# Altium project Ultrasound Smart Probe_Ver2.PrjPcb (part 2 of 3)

## Sheet Sht04--FPGA Power Supply.SchDoc: LVPS FPGA
size 431 x 279 mm; Date: Not shown in title block; ApprovedBy: Not shown in title block; CheckedBy: Not shown in title block; Author: Not shown in title block; CompanyName: Not shown in title block; DrawnBy: Bill.Xu; Engineer: Bill.Xu; Organization: Not shown in title block; Address1: Not shown in title block; Address2: Not shown in title block; Address3: Not shown in title block; Address4: Not shown in title block; DocumentNumber: 1; Revision: Use project parameter SCH_Rev; SheetNumber: 4; SheetTotal: 7; PageSetup: Record=PageOptions¦CenterHorizontal=True¦CenterVertical=True¦PrintScale=1.00¦XCorrection=1.00¦YCorrection=1.00¦PrintKind=0¦BorderSize=5000000¦LeftOffset=0¦BottomOffset=0¦Orientation=2¦PaperLength=1000¦PaperWidth=1000¦Scale=100¦PaperSource=15¦PrintQuality=600¦MediaType=1¦DitherType=10¦PaperKind=Letter¦PrintScaleMode=1
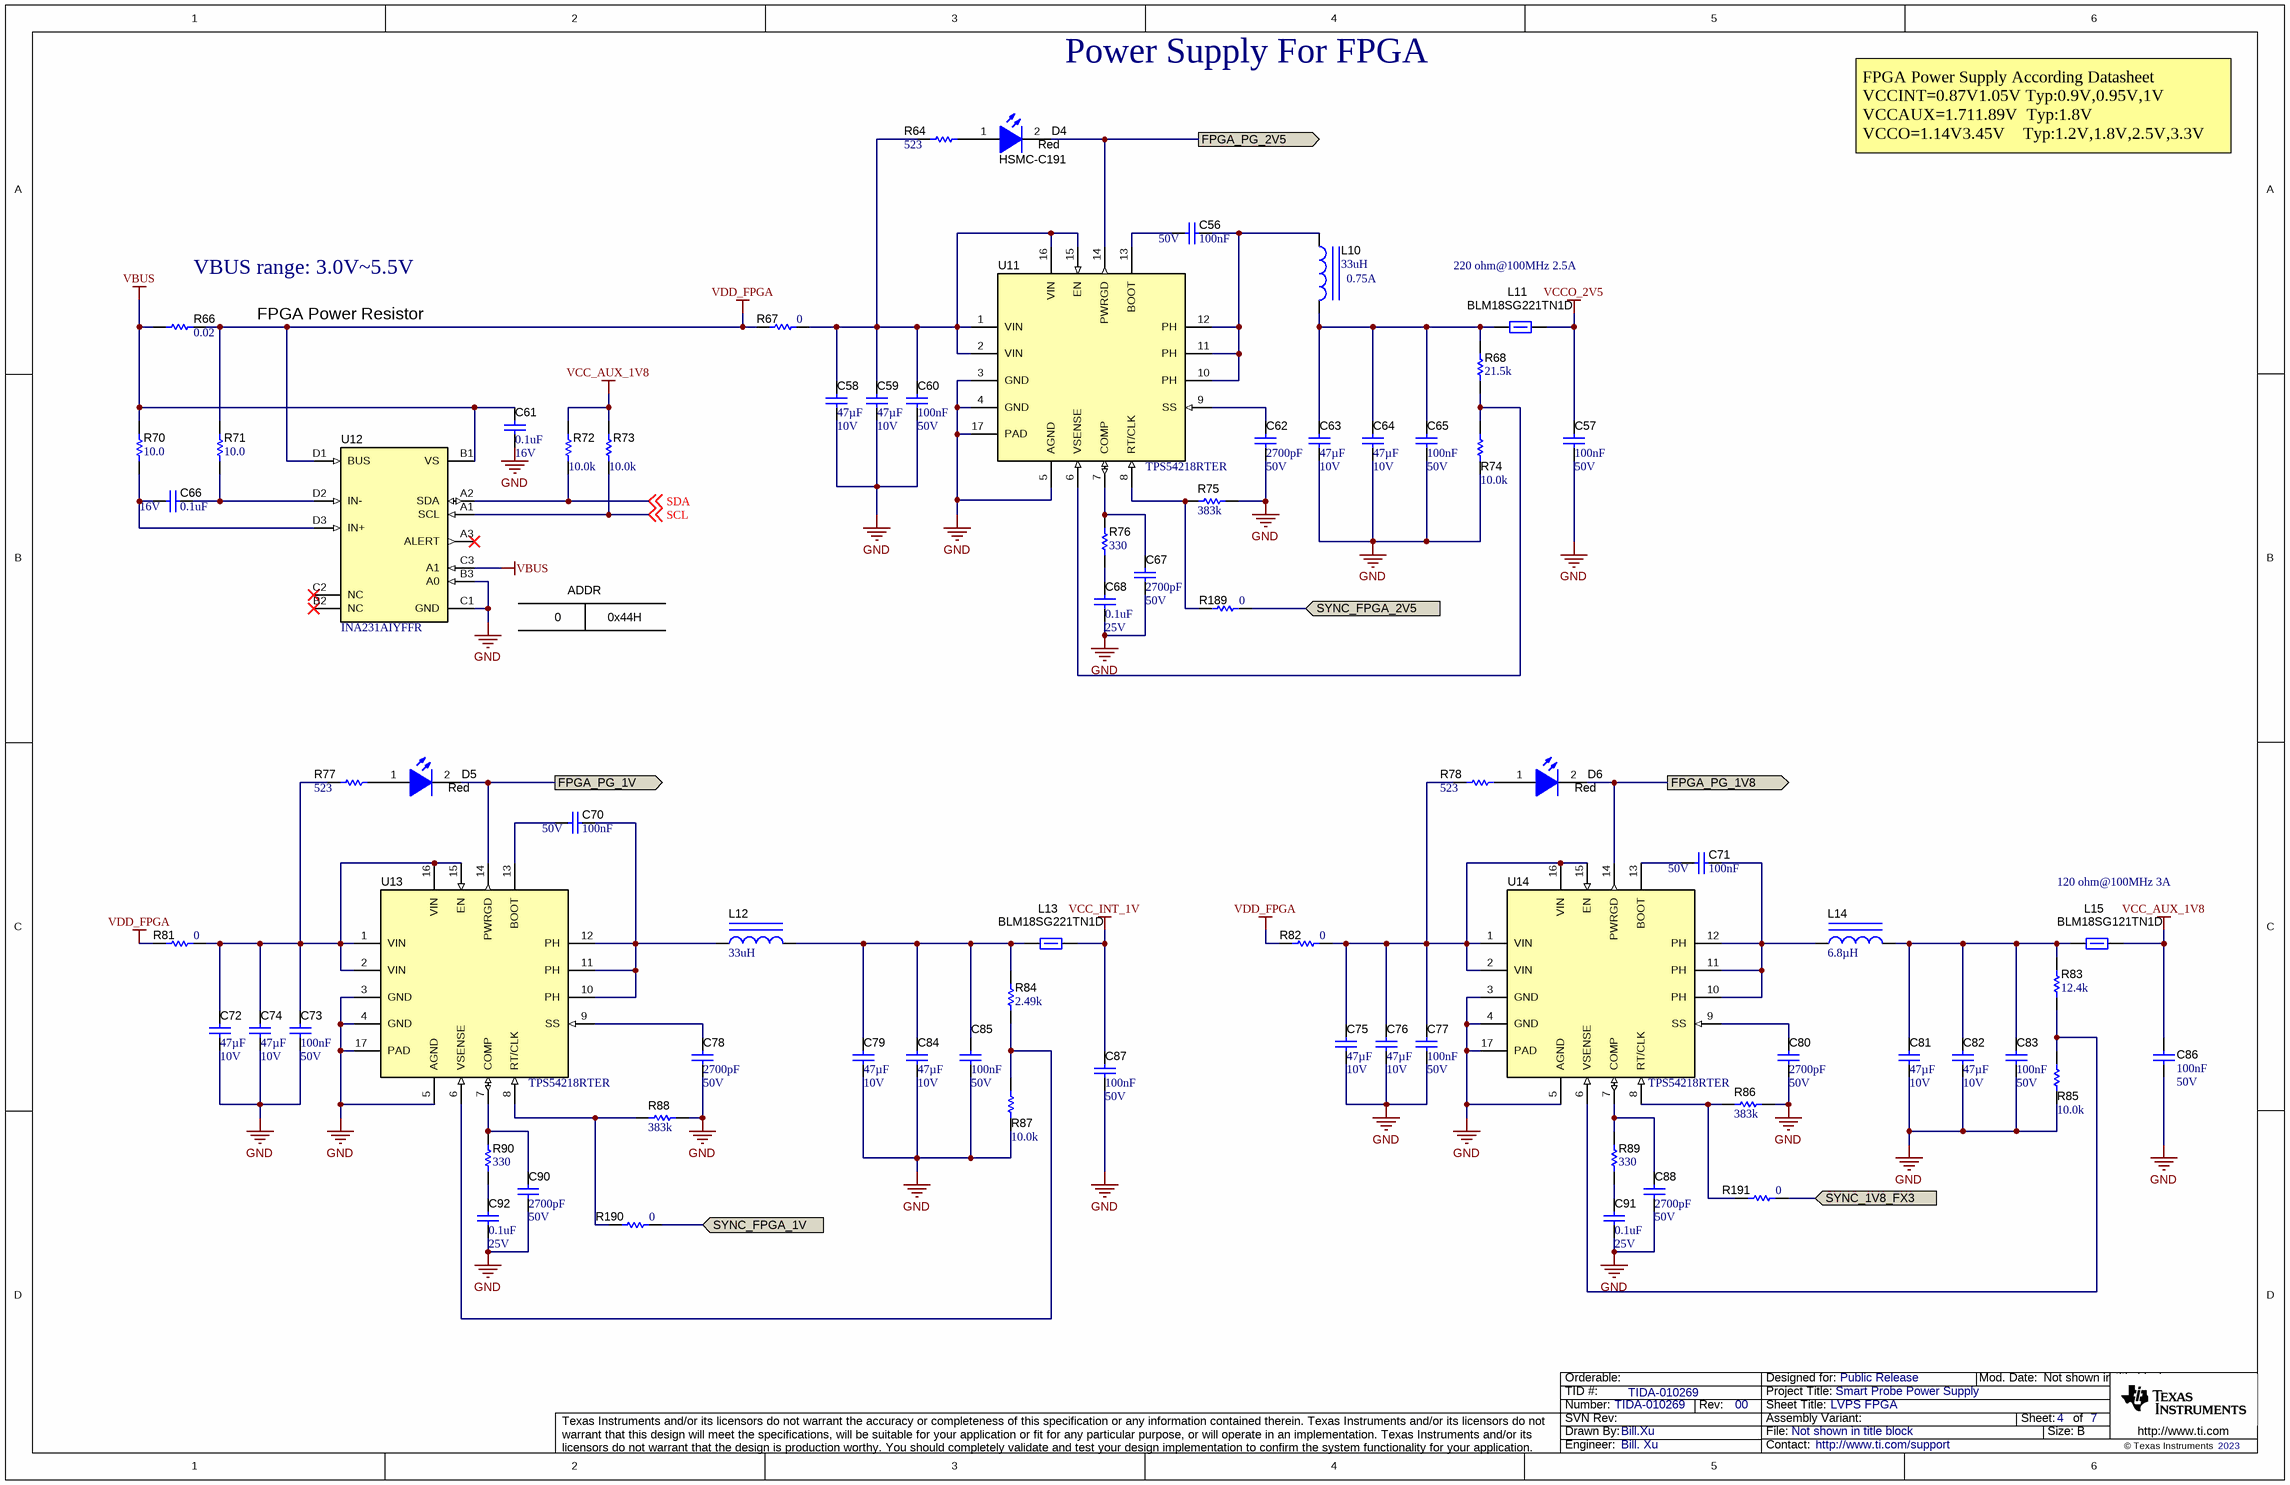
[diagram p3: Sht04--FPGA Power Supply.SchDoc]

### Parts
C56  Cap_F: 100nF  VDC_V: 50V  [0603]  (hidden comment: 885012206095)
C57  Cap_F: 100nF  VDC_V: 50V  [0603]  (hidden comment: 885012206095)
C58  VDC_V: 10V  ValueDisplayed: 47µF  [0805_HV]  (hidden comment: GRM21BR61A476ME15L)
C59  VDC_V: 10V  ValueDisplayed: 47µF  [0805_HV]  (hidden comment: GRM21BR61A476ME15L)
C60  Cap_F: 100nF  VDC_V: 50V  [0603]  (hidden comment: 885012206095)
C61  VDC_V: 16V  ValueDisplayed: 0.1uF  [0201_033]  (hidden comment: C0603X6S1C104K030BC)
C62  VDC_V: 50V  ValueDisplayed: 2700pF  [0402]  (hidden comment: GRM155R71H272KA01D)
C63  VDC_V: 10V  ValueDisplayed: 47µF  [0805_HV]  (hidden comment: GRM21BR61A476ME15L)
C64  VDC_V: 10V  ValueDisplayed: 47µF  [0805_HV]  (hidden comment: GRM21BR61A476ME15L)
C65  Cap_F: 100nF  VDC_V: 50V  [0603]  (hidden comment: 885012206095)
C66  VDC_V: 16V  ValueDisplayed: 0.1uF  [0201_033]  (hidden comment: C0603X6S1C104K030BC)
C67  VDC_V: 50V  ValueDisplayed: 2700pF  [0402]  (hidden comment: GRM155R71H272KA01D)
C68  VDC_V: 25V  ValueDisplayed: 0.1uF  [0402]  (hidden comment: GRM155R61E104KA87D)
C70  Cap_F: 100nF  VDC_V: 50V  [0603]  (hidden comment: 885012206095)
C71  Cap_F: 100nF  VDC_V: 50V  [0603]  (hidden comment: 885012206095)
C72  VDC_V: 10V  ValueDisplayed: 47µF  [0805_HV]  (hidden comment: GRM21BR61A476ME15L)
C73  Cap_F: 100nF  VDC_V: 50V  [0603]  (hidden comment: 885012206095)
C74  VDC_V: 10V  ValueDisplayed: 47µF  [0805_HV]  (hidden comment: GRM21BR61A476ME15L)
C75  VDC_V: 10V  ValueDisplayed: 47µF  [0805_HV]  (hidden comment: GRM21BR61A476ME15L)
C76  VDC_V: 10V  ValueDisplayed: 47µF  [0805_HV]  (hidden comment: GRM21BR61A476ME15L)
C77  Cap_F: 100nF  VDC_V: 50V  [0603]  (hidden comment: 885012206095)
C78  VDC_V: 50V  ValueDisplayed: 2700pF  [0402]  (hidden comment: GRM155R71H272KA01D)
C79  VDC_V: 10V  ValueDisplayed: 47µF  [0805_HV]  (hidden comment: GRM21BR61A476ME15L)
C80  VDC_V: 50V  ValueDisplayed: 2700pF  [0402]  (hidden comment: GRM155R71H272KA01D)
C81  VDC_V: 10V  ValueDisplayed: 47µF  [0805_HV]  (hidden comment: GRM21BR61A476ME15L)
C82  VDC_V: 10V  ValueDisplayed: 47µF  [0805_HV]  (hidden comment: GRM21BR61A476ME15L)
C83  Cap_F: 100nF  VDC_V: 50V  [0603]  (hidden comment: 885012206095)
C84  VDC_V: 10V  ValueDisplayed: 47µF  [0805_HV]  (hidden comment: GRM21BR61A476ME15L)
C85  Cap_F: 100nF  VDC_V: 50V  [0603]  (hidden comment: 885012206095)
C86  Cap_F: 100nF  VDC_V: 50V  [0402]  (hidden comment: GRM155R61E104KA87D)
C87  Cap_F: 100nF  VDC_V: 50V  [0402]  (hidden comment: GRM155R61E104KA87D)
C88  VDC_V: 50V  ValueDisplayed: 2700pF  [0402]  (hidden comment: GRM155R71H272KA01D)
C90  VDC_V: 50V  ValueDisplayed: 2700pF  [0402]  (hidden comment: GRM155R71H272KA01D)
C91  VDC_V: 25V  ValueDisplayed: 0.1uF  [0402]  (hidden comment: GRM155R61E104KA87D)
C92  VDC_V: 25V  ValueDisplayed: 0.1uF  [0402]  (hidden comment: GRM155R61E104KA87D)
D4  HSMC-C191  value Red  [HSMx-C191_Red]
D5  value Red  [HSMx-C191_Red]  (hidden comment: HSMC-C191)
D6  value Red  [HSMx-C191_Red]  (hidden comment: HSMC-C191)
L10  ValueDisplayed: 33uH  [WE-TPC-LH]  (hidden comment: 744053330)
L11  BLM18SG221TN1D  [0603]
L12  ValueDisplayed: 33uH  [WE-TPC-LH]  (hidden comment: 744053330)
L13  BLM18SG221TN1D  [0603]
L14  ValueDisplayed: 6.8µH  [NRS5030]  (hidden comment: NRS5030T6R8MMGJV)
L15  BLM18SG121TN1D  [0603]
R64  ValueDisplayed: 523  [0402]  (hidden comment: CRCW0402523RFKED)
R66  ValueDisplayed: 0.02  [WSLP0805]  (hidden comment: WSLP0805R0200FEB)
R67  ValueDisplayed: 0  [0805_HV]  (hidden comment: RC0805JR-070RL)
R68  ValueDisplayed: 21.5k  [0201]  (hidden comment: RC0201FR-0721K5L)
R70  ValueDisplayed: 10.0  [0201]  (hidden comment: RC0201FR-7D10RL)
R71  ValueDisplayed: 10.0  [0201]  (hidden comment: RC0201FR-7D10RL)
R72  ValueDisplayed: 10.0k  [0201]  (hidden comment: RC0201FS-7D10KL)
R73  ValueDisplayed: 10.0k  [0201]  (hidden comment: RC0201FS-7D10KL)
R74  ValueDisplayed: 10.0k  [0201]  (hidden comment: RC0201FS-7D10KL)
R75  ValueDisplayed: 383k  [0201]  (hidden comment: RC0201FR-07383KL)
R76  ValueDisplayed: 330  [0402]  (hidden comment: CRCW0402160RJNED)
R77  ValueDisplayed: 523  [0402]  (hidden comment: CRCW0402523RFKED)
R78  ValueDisplayed: 523  [0402]  (hidden comment: CRCW0402523RFKED)
R81  ValueDisplayed: 0  [0805_HV]  (hidden comment: RC0805JR-070RL)
R82  ValueDisplayed: 0  [0805_HV]  (hidden comment: RC0805JR-070RL)
R83  ValueDisplayed: 12.4k  [0201]  (hidden comment: RC0201FR-0712K4L)
R84  ValueDisplayed: 2.49k  [0201]  (hidden comment: RC0201FR-7D2K49L)
R85  ValueDisplayed: 10.0k  [0201]  (hidden comment: RC0201FS-7D10KL)
R86  ValueDisplayed: 383k  [0201]  (hidden comment: RC0201FR-07383KL)
R87  ValueDisplayed: 10.0k  [0201]  (hidden comment: RC0201FS-7D10KL)
R88  ValueDisplayed: 383k  [0201]  (hidden comment: RC0201FR-07383KL)
R89  ValueDisplayed: 330  [0402]  (hidden comment: CRCW0402160RJNED)
R90  ValueDisplayed: 330  [0402]  (hidden comment: CRCW0402160RJNED)
R189  ValueDisplayed: 0  [0201]  (hidden comment: CRCW02010000Z0ED)
R190  ValueDisplayed: 0  [0201]  (hidden comment: CRCW02010000Z0ED)
R191  ValueDisplayed: 0  [0201]  (hidden comment: CRCW02010000Z0ED)
U11  TPS54218RTER  [RTE0016F]
U12  INA231AIYFFR  [YFF0012AKAD]
U13  TPS54218RTER  [RTE0016F]
U14  TPS54218RTER  [RTE0016F]

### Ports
FPGA_PG_1V8 (out), FPGA_PG_1V (out), FPGA_PG_2V5 (out), SYNC_1V8_FX3 (in), SYNC_FPGA_1V (in), SYNC_FPGA_2V5 (in)

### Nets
GND: C57.2 C58.2 C59.2 C60.2 C61.2 C62.2 C63.2 C64.2 C65.2 C67.2 C68.2 C72.2 C73.2 C74.2 C75.2 C76.2 C77.2 C78.2 C79.2 C80.2 C81.2 C82.2 C83.1 C84.2 C85.2 C86.2 C87.2 C88.2 C90.2 C91.2 C92.2 R74.1 R75.2 R85.1 R86.2 R87.1 R88.2 U11.3(GND) U11.4(GND) U11.5(AGND) U11.17(PAD) U12.B3(A0) U12.C1(GND) U13.3(GND) U13.4(GND) U13.5(AGND) U13.17(PAD) U14.3(GND) U14.4(GND) U14.5(AGND) U14.17(PAD)
VBUS: C61.1 R66.1 R70.2 U12.B1(VS) U12.C3(A1)
VCC_AUX_1V8: C86.1 L15.2 R72.2 R73.2
VCC_INT_1V: C87.1 L13.2
VCCO_2V5: C57.1 L11.2
VDD_FPGA: R66.2 R67.1 R71.2 R81.1 R82.1 U12.D1(BUS)
FPGA_PG_1V: D5.2(K) U13.14(PWRGD) ; port FPGA_PG_1V
FPGA_PG_1V8: D6.2(K) U14.14(PWRGD) ; port FPGA_PG_1V8
FPGA_PG_2V5: D4.2(K) U11.14(PWRGD) ; port FPGA_PG_2V5
SCL: R73.1 U12.A1(SCL) ; off-sheet SCL
SDA: R72.1 U12.A2(SDA) ; off-sheet SDA
SYNC_1V8_FX3: R191.2 ; port SYNC_1V8_FX3
SYNC_FPGA_1V: R190.2 ; port SYNC_FPGA_1V
SYNC_FPGA_2V5: R189.2 ; port SYNC_FPGA_2V5
NetC56_1: C56.1 L10.1 U11.10(PH) U11.11(PH) U11.12(PH)
NetC56_2: C56.2 U11.13(BOOT)
NetC58_1: C58.1 C59.1 C60.1 R64.1 R67.2 U11.1(VIN) U11.2(VIN) U11.15(EN) U11.16(VIN)
NetC62_1: C62.1 U11.9(SS)
NetC63_1: C63.1 C64.1 C65.1 L10.2 L11.1 R68.2
NetC66_1: C66.1 R70.1 U12.D3(IN+)
NetC66_2: C66.2 R71.1 U12.D2(IN-)
NetC67_1: C67.1 R76.2 U11.7(COMP)
NetC68_1: C68.1 R76.1
NetC70_1: C70.1 L12.1 U13.10(PH) U13.11(PH) U13.12(PH)
NetC70_2: C70.2 U13.13(BOOT)
NetC71_1: C71.1 L14.1 U14.10(PH) U14.11(PH) U14.12(PH)
NetC71_2: C71.2 U14.13(BOOT)
NetC72_1: C72.1 C73.1 C74.1 R77.1 R81.2 U13.1(VIN) U13.2(VIN) U13.15(EN) U13.16(VIN)
NetC75_1: C75.1 C76.1 C77.1 R78.1 R82.2 U14.1(VIN) U14.2(VIN) U14.15(EN) U14.16(VIN)
NetC78_1: C78.1 U13.9(SS)
NetC79_1: C79.1 C84.1 C85.1 L12.2 L13.1 R84.2
NetC80_1: C80.1 U14.9(SS)
NetC81_1: C81.1 C82.1 C83.2 L14.2 L15.1 R83.2
NetC88_1: C88.1 R89.2 U14.7(COMP)
NetC90_1: C90.1 R90.2 U13.7(COMP)
NetC91_1: C91.1 R89.1
NetC92_1: C92.1 R90.1
NetD4_1: D4.1(A) R64.2
NetD5_1: D5.1(A) R77.2
NetD6_1: D6.1(A) R78.2
NetR68_1: R68.1 R74.2 U11.6(VSENSE)
NetR75_1: R75.1 R189.1 U11.8(RT/CLK)
NetR83_1: R83.1 R85.2 U14.6(VSENSE)
NetR84_1: R84.1 R87.2 U13.6(VSENSE)
NetR86_1: R86.1 R191.1 U14.8(RT/CLK)
NetR88_1: R88.1 R190.1 U13.8(RT/CLK)

Not connected (* = marked no-connect by the designer): U12 A3(ALERT)* B2(NC)* C2(NC)*

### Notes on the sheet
- Power Supply For FPGA
- FPGA Power Supply According Datasheet
  VCCINT=0.87V1.05V Typ:0.9V,0.95V,1V
  VCCAUX=1.711.89V  Typ:1.8V
  VCCO=1.14V3.45V    Typ:1.2V,1.8V,2.5V,3.3V
- (near R66) VBUS range: 3.0V~5.5V
- (near L10) 0.75A
- 220 ohm@100MHz 2.5A
- FPGA Power Resistor
- 0
- ADDR
- 0x44H
- 120 ohm@100MHz 3A

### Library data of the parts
C56 C57 C60 C65 C70 C71 C73 C77 C83 C85 = CMP-0006837-2: CAP, CERM, 0.1 uF, 50 V, +/- 10%, X7R, 0603; Manufacturer: Wurth Elektronik; TaMin_C: -55°C; Polarized: N; SizeAreaWB_mm2: 4.68; Value1: Unknown; U/M: EA; Value: 0.1uF; TaMax_C: 125°C; SizeZ_mm: 1; SizeX_mm: 1.6; SizeY_mm: 0.8; SizeArea_mm2: 1.28; AEC Category: Q200
C58 C59 C63 C64 C72 C74-C76 C79 C81 C82 C84 = CMP-0078699-1: CAP, CERM, 47 µF, 10 V,+/- 20%, X5R, 0805; Manufacturer: MuRata; TaMin_C: -55°C; Polarized: N; Green_Lifecycle: Active; SizeAreaWB_mm2: 6.75; Green_REACh: Passed; U/M: EA; Value: 47uF; TaMax_C: 85°C; SizeZ_mm: 1.45; SizeX_mm: 2; SizeY_mm: 1.25; Cap_Case: 0805; SizeArea_mm2: 2.5; AEC Category: Q200
C61 C66 = CMP-0009637-1: CAP, CERM, 0.1 uF, 16 V, +/- 10%, X6S, 0201; Manufacturer: TDK; TaMin_C: -55°C; Polarized: N; SizeAreaWB_mm2: 2.08; Value1: Unknown; U/M: EA; Value: 0.1uF; TaMax_C: 105°C; SizeZ_mm: 0.33; SizeX_mm: 0.6; SizeY_mm: 0.3; Cap_Case: 0201; SizeArea_mm2: 0.18; Cap_F: 100nF; AEC Category: Q200
C62 C67 C78 C80 C88 C90 = CMP-0006686-1: CAP, CERM, 2700 pF, 50 V, +/- 10%, X7R, 0402; Manufacturer: MuRata; TaMin_C: -55°C; Polarized: N; SizeAreaWB_mm2: 3; Value1: Unknown; U/M: EA; Value: 2700pF; TaMax_C: 125°C; SizeZ_mm: 0.6; SizeX_mm: 1; SizeY_mm: 0.5; Cap_F: 2.7nF; AEC Category: Q200
C68 C91 C92 = CMP-0006607-1: CAP, CERM, 0.1 uF, 25 V, +/- 10%, X5R, 0402; Manufacturer: MuRata; TaMin_C: -55°C; Polarized: N; SizeAreaWB_mm2: 3; Value1: Unknown; U/M: EA; Value: 0.1uF; TaMax_C: 85°C; SizeZ_mm: 0.6; SizeX_mm: 1; SizeY_mm: 0.5; Cap_F: 100nF; AEC Category: Q200
C86 C87 = CMP-0006837-2: CAP, CERM, 0.1 uF, 50 V, +/- 10%, X7R, 0603; Manufacturer: Wurth Elektronik; PartNumber: 885012206095; TaMin_C: -55°C; Polarized: N; SizeAreaWB_mm2: 4.68; Value1: Unknown; U/M: EA; Value: 0.1uF; TaMax_C: 125°C; SizeZ_mm: 1; SizeX_mm: 1.6; SizeY_mm: 0.8; Cap_Case: 0603; SizeArea_mm2: 1.28; AEC Category: Q200
D4-D6 = CMP-0078541-2: LED, Red, SMD; Manufacturer: Avago; Vf_V: 1.9V; SizeX_mm: 1.6; SizeY_mm: 0.8; Tjmax_C: 95°C; Io_A: 20mA; SizeAreaWB_mm2: 4.68; Value1: W; Angle: 170; SizeArea_mm2: 1.28; Vr_V: 5V; Type: AlInGaP; SizeZ_mm: 0.7
L10 L12 = CMP-0064424-1: Inductor, Shielded Drum Core, Ferrite, 33 uH, 0.75 A, 0.155 ohm, SMD; Manufacturer: Wurth Elektronik; Isat: 0.75A @ 35% inductance drop; Irms: 0.9A @ 30C rise; Green_Lifecycle: Active; SizeAreaWB_mm2: 60.84; DCR_ohm: 0.155; Green_REACh: Passed; Value: 33uH; Imax_A: 750mA; SizeZ_mm: 2.8; SizeX_mm: 5.8; Value2: 0.75A; SizeArea_mm2: 33.64; Ind_H: 33µH; AEC Category: Q200
L11 L13 = CMP-0003353-1: Ferrite Bead, 220 ohm @ 100 MHz, 2.5 A, 0603; Manufacturer: MuRata; ZTyp@100MHz_Ohm: 220; SizeAreaWB_mm2: 4.68; DCR_ohm: 40m; Value1: 0.04 ohm; Value: 220 ohm; Imax_A: 2.5A; SizeZ_mm: 1; SizeX_mm: 1.6; SizeY_mm: 0.8; SizeArea_mm2: 1.28
L14 = CMP-0081757-1: Inductor, Shielded, Ferrite, 6.8 µH, 2.3 A, 0.0676 ohm, AEC-Q200 Grade 1, SMD; Manufacturer: Taiyo Yuden; Isat: 2.5A @ 30% inductance drop; Irms: 2A @ 40C rise; SizeAreaWB_mm2: 34.81; DCR_ohm: 67.6m; Value: 6.8uH; Imax_A: 2.3A; SizeZ_mm: 3.1; SizeX_mm: 4.9; SizeArea_mm2: 24.01; AEC Qualified: Y; AEC Grade: 1; AEC Category: Q200
L15 = CMP-0003352-2: Ferrite Bead, 120 ohm @ 100 MHz, 3 A, 0603; Manufacturer: MuRata; ZTyp@100MHz_Ohm: 120; SizeAreaWB_mm2: 4.68; DCR_ohm: 25m; Value1: 0.025 ohm; Value: 120 ohm; Imax_A: 3A; SizeZ_mm: 1; SizeX_mm: 1.6; SizeY_mm: 0.8; SizeArea_mm2: 1.28
R64 R77 R78 = CMP-0026440-2: RES, 523, 1%, 0.063 W, AEC-Q200 Grade 0, 0402; Manufacturer: Vishay-Dale; Power_W: 63mW; TempCo: 100 ppm/C; Value_Code: 523R; Value: 523; EIA_Code: E96; SizeX_mm: 1; SizeY_mm: 0.5; SizeZ_mm: 0.6; Value2: 0.063W; AEC Qualified: Y; VDC_V: 50V; AEC Category: Q200; AEC Grade: 0
R66 = CMP-0021986-1: RES, 0.02, 1%, 0.5 W, 0805; Manufacturer: Vishay-Dale; Power_W: 500mW; TempCo: 75 ppm/C; Value_Code: R020; U/M: EA; Value: 0.02; EIA_Code: E96; Res_ohm: 20m; SizeX_mm: 2.03; SizeY_mm: 1.27; SizeZ_mm: 0.635; Value2: 0.5W; SizeArea_mm2: 2.5781; AEC Qualified: N; AEC Category: Q200
R67 R81 R82 = CMP-0020803-2: RES, 0, 5%, 0.125 W, 0805; Manufacturer: Yageo America; Power_W: 125mW; TempCo: 200 ppm/C; Value_Code: 0000; U/M: EA; Value: 0; EIA_Code: E24; SizeX_mm: 2; SizeY_mm: 1.25; SizeZ_mm: 1.45; Value2: 0.125W; SizeArea_mm2: 2.5; VDC_V: 150V; AEC Category: Q200
R68 = CMP-0027485-1: RES, 21.5 k, 1%, 0.05 W, 0201; Manufacturer: Yageo America; Power_W: 50mW; TempCo: 200 ppm/C; Value_Code: 21k5; U/M: EA; Value: 21.5k; EIA_Code: E96; SizeX_mm: 0.6; SizeY_mm: 0.3; SizeZ_mm: 0.26; Value2: 0.05W; SizeArea_mm2: 0.18; AEC Qualified: N; VDC_V: 25V; AEC Category: Q200
R70 R71 = CMP-0027946-1: RES, 10.0, 1%, 0.05 W, 0201; Manufacturer: Yageo America; Power_W: 50mW; TempCo: 350 ppm/C; Value_Code: 10R0; U/M: EA; Value: 10.0; EIA_Code: E96; Res_ohm: 10; SizeX_mm: 0.6; SizeY_mm: 0.3; SizeZ_mm: 0.26; Value2: 0.05W; SizeArea_mm2: 0.18; AEC Qualified: N; VDC_V: 25V; AEC Category: Q200
R72-R74 R85 R87 = CMP-0028071-1: RES SMD 10K OHM 1% 1/20W 0201; Manufacturer: Samsung Electro-Mechanics; PartNumber: RC0603F103CS; Power_W: 50mW; TempCo: 200 ppm/C; Value_Code: 10k0; U/M: EA; Value: 10.0k; EIA_Code: E96; SizeX_mm: 0.6; SizeY_mm: 0.3; SizeZ_mm: 0.26; Value2: 0.05W; SizeArea_mm2: 0.18; AEC Qualified: N; VDC_V: 25V; AEC Category: Q200
R75 R86 R88 = CMP-0027640-1: RES, 383 k, 1%, 0.05 W, 0201; Manufacturer: Yageo America; Power_W: 50mW; TempCo: 200 ppm/C; U/M: EA; Value: 383k; EIA_Code: E96; SizeX_mm: 0.6; SizeY_mm: 0.3; SizeZ_mm: 0.26; Value2: 0.05W; SizeArea_mm2: 0.18; AEC Qualified: N; VDC_V: 25V; AEC Category: Q200
R76 R89 R90 = CMP-0026845-3: RES SMD 330 OHM 1% 1/10W 0402; Manufacturer: Panasonic Electronic Components; PartNumber: ERJ-2RKF3300X; Power_W: 63mW; TempCo: 200 ppm/C; Value_Code: 160R; Value1: 5%; Value: 160; EIA_Code: E24; SizeX_mm: 1; SizeY_mm: 0.5; SizeZ_mm: 0.6; Value2: 0.063W; AEC Qualified: Y; VDC_V: 50V; AEC Category: Q200; AEC Grade: 0
R83 = CMP-0027335-2: RES, 12.4 k, 1%, 0.05 W, 0201; Manufacturer: Yageo America; Power_W: 50mW; TempCo: 200 ppm/C; Value_Code: 12k4; U/M: EA; Value: 12.4k; EIA_Code: E96; SizeX_mm: 0.6; SizeY_mm: 0.3; SizeZ_mm: 0.26; Value2: 0.05W; SizeArea_mm2: 0.18; AEC Qualified: N; VDC_V: 25V; AEC Category: Q200
R84 = CMP-0027996-1: RES, 2.49 k, 1%, 0.05 W, 0201; Manufacturer: Yageo America; Power_W: 50mW; TempCo: 200 ppm/C; Value_Code: 2k49; U/M: EA; Value: 2.49k; EIA_Code: E96; SizeX_mm: 0.6; SizeY_mm: 0.3; SizeZ_mm: 0.26; Value2: 0.05W; SizeArea_mm2: 0.18; AEC Qualified: N; VDC_V: 25V; AEC Category: Q200
R189-R191 = CMP-0027008-1: RES, 0, 5%, 0.05 W, 0201; Manufacturer: Vishay-Dale; Power_W: 50mW; TempCo: ppm/C; Value_Code: 0000; U/M: EA; Value: 0; EIA_Code: E24; SizeX_mm: 0.6; SizeY_mm: 0.3; SizeZ_mm: 0.26; Value2: 0.05W; SizeArea_mm2: 0.18; AEC Qualified: N; AEC Category: Q200
U11 U14 = CMP-0073970-3: 2.95V to 6V Input, 2A Synchronous Step-Down SWIFT(TM) Converter, RTE0016F (WQFN-16); Alternate PartNumber: TPS54218RTET; Alternate Manufacturer: Texas Instruments; Green_Lifecycle: Active; SizeAreaWB_mm2: 16.0; Green_REACh: Passed; SizeZ_mm: 0.8; SizeX_mm: 3.0; SizeArea_mm2: 9.0; CompType: IC; AEC Category: Q200; AEC Qualified: N
U12 = CMP-0065450-1: 28-V, Bi-Directional, Zero-Drift, Low-/High-Side, I2C Out Current/Power Monitor w/ Alert in WCSP, YFF0012AKAD (DSBGA-12); Alternate PartNumber: INA231AIYFFT; Alternate Manufacturer: Texas Instruments; Green_Lifecycle: Active; SizeAreaWB_mm2: 6.313872; Green_REACh: Passed; U/M: EA; SizeZ_mm: 0.625; SizeX_mm: 1.388; SizeY_mm: 1.644; SizeArea_mm2: 2.281872; CompType: IC
U13 = CMP-0073970-1: 2.95V to 6V Input, 2A Synchronous Step-Down SWIFT(TM) Converter, RTE0016F (WQFN-16); Alternate PartNumber: TPS54218RTET; Alternate Manufacturer: Texas Instruments; Green_Lifecycle: Active; SizeAreaWB_mm2: 16.0; Green_REACh: Passed; U/M: EA; SizeZ_mm: 0.8; SizeX_mm: 3.0; SizeArea_mm2: 9.0; CompType: IC

## Sheet Sht05--TX-RX Supply 1.8V and 1.15V.SchDoc: LVPS RX Supply 1.8V and 1.15V
size 431 x 279 mm; Date: Not shown in title block; ApprovedBy: Not shown in title block; CheckedBy: Not shown in title block; Author: Not shown in title block; CompanyName: Not shown in title block; DrawnBy: Bill.Xu; Engineer: Bill.Xu; Organization: Not shown in title block; Address1: Not shown in title block; Address2: Not shown in title block; Address3: Not shown in title block; Address4: Not shown in title block; DocumentNumber: 1; Revision: Use project parameter SCH_Rev; SheetNumber: 5; SheetTotal: 7; PageSetup: Record=PageOptions¦CenterHorizontal=True¦CenterVertical=True¦PrintScale=1.00¦XCorrection=1.00¦YCorrection=1.00¦PrintKind=0¦BorderSize=5000000¦LeftOffset=0¦BottomOffset=0¦Orientation=2¦PaperLength=1000¦PaperWidth=1000¦Scale=100¦PaperSource=15¦PrintQuality=600¦MediaType=1¦DitherType=10¦PaperKind=Letter¦PrintScaleMode=1
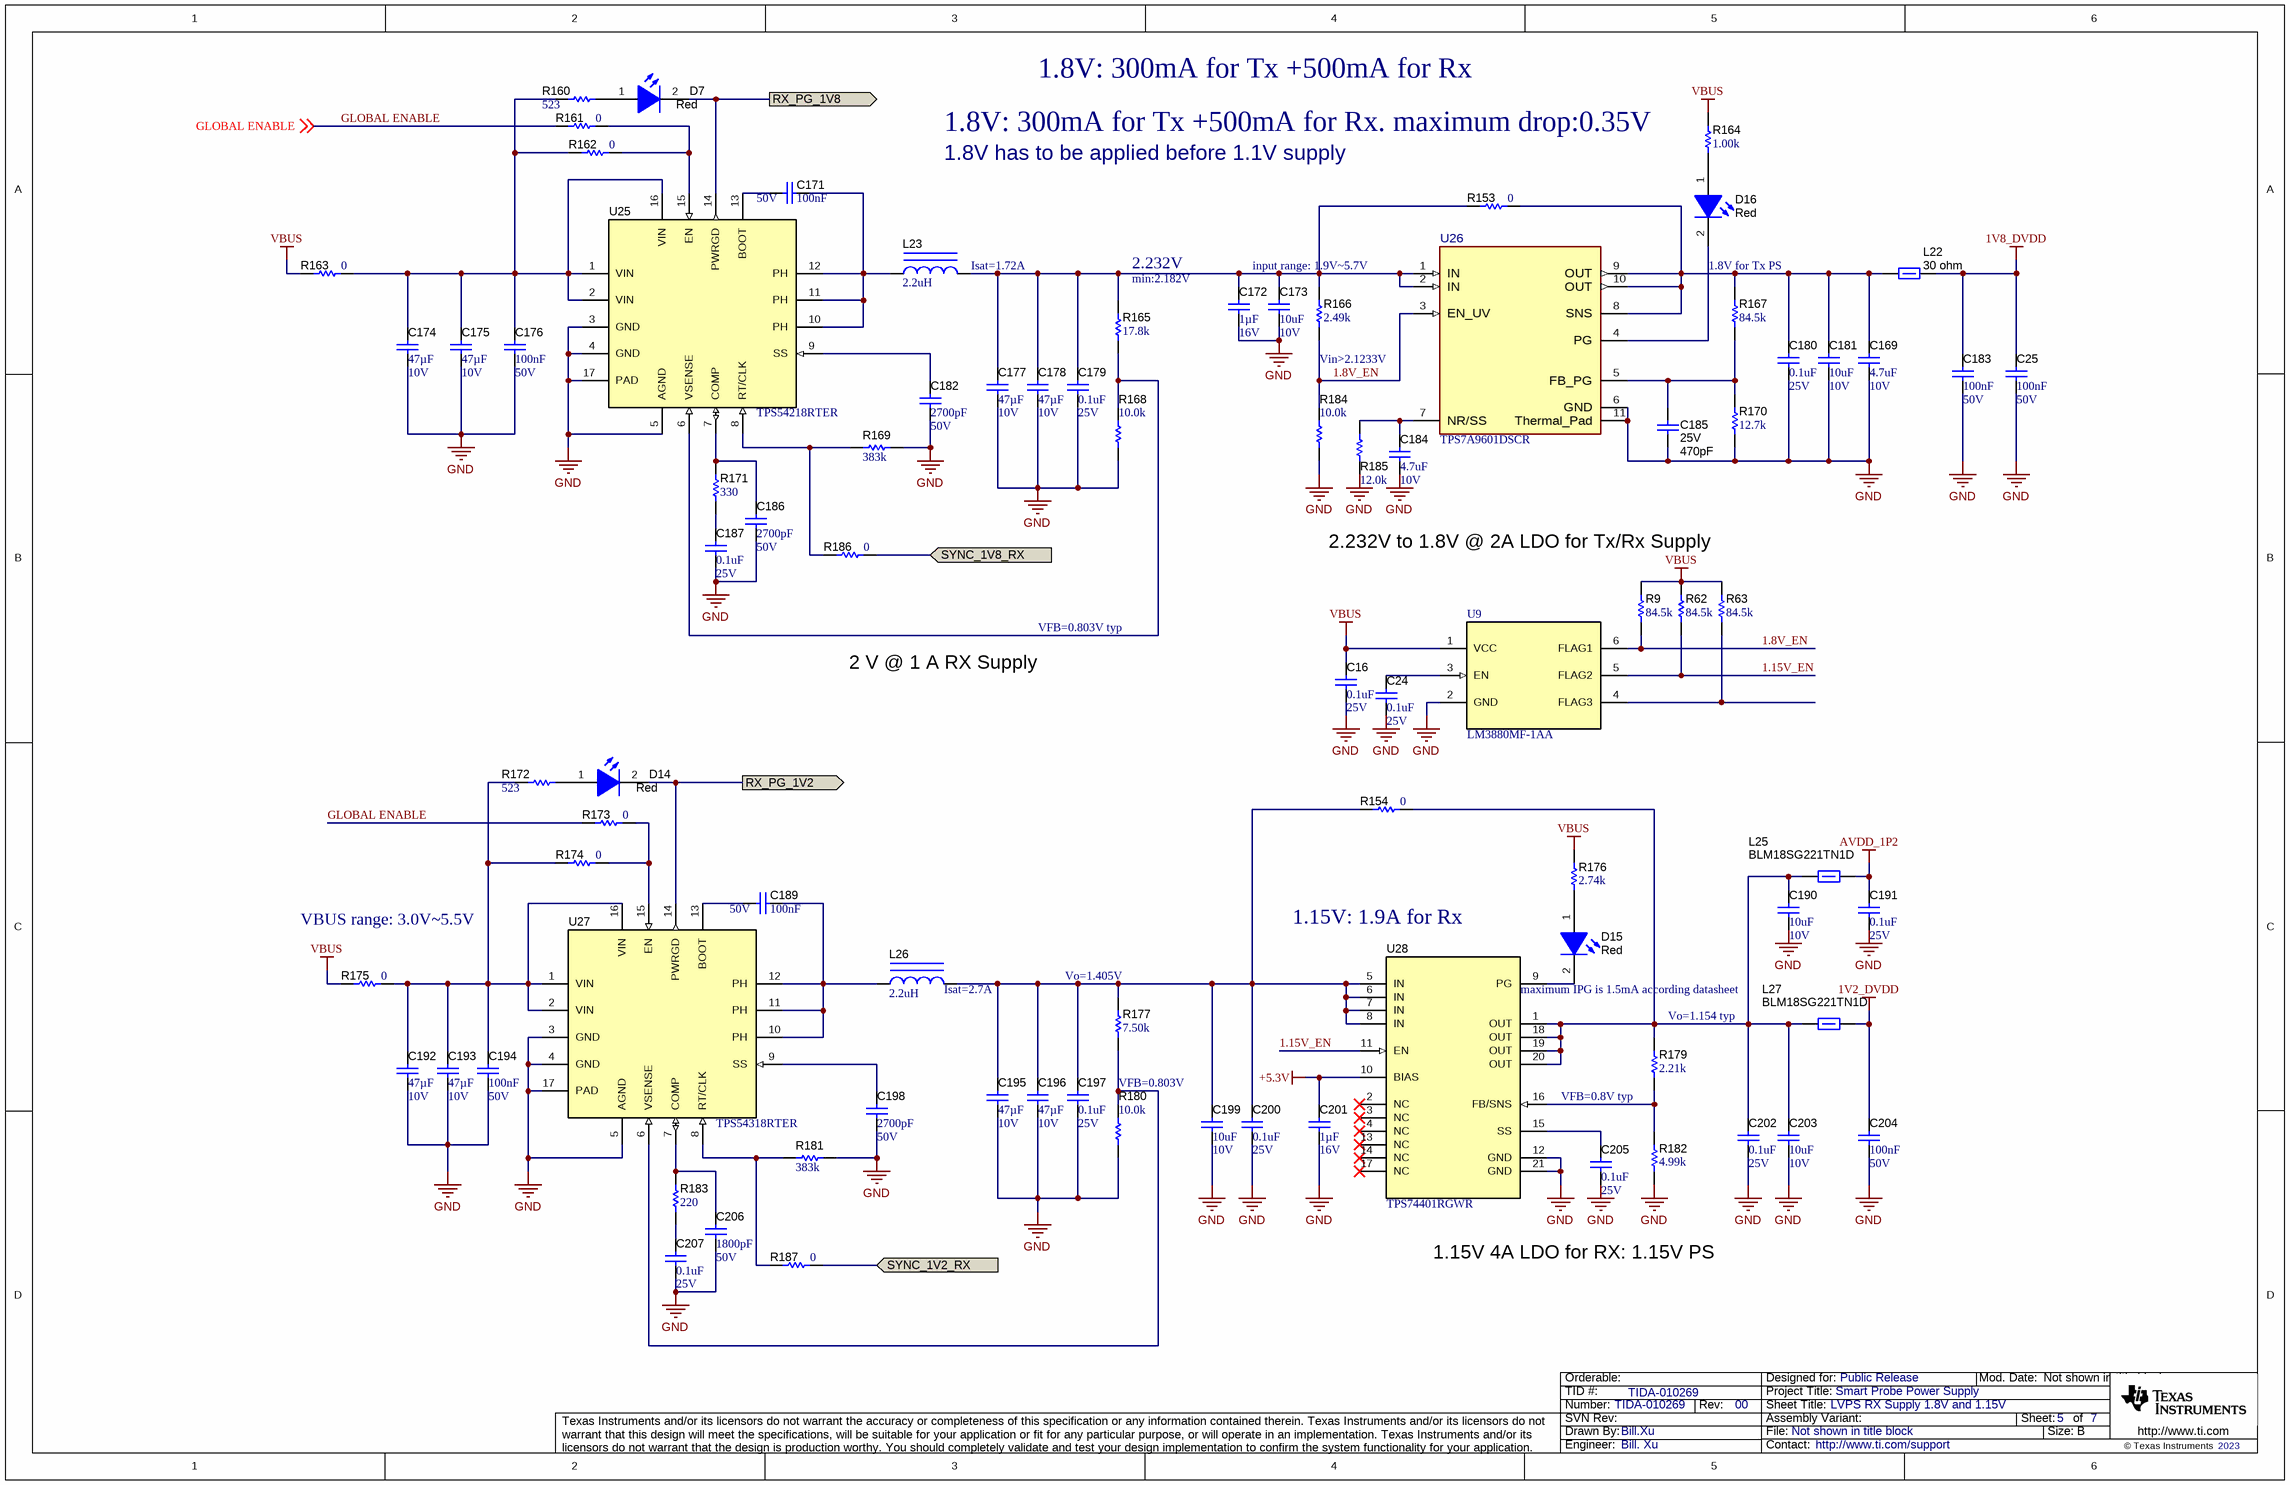
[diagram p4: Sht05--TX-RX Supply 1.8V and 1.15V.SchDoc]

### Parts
C16  VDC_V: 25V  ValueDisplayed: 0.1uF  [0402]  (hidden comment: GRM155R61E104KA87D)
C24  VDC_V: 25V  ValueDisplayed: 0.1uF  [0402]  (hidden comment: GRM155R61E104KA87D)
C25  Cap_F: 100nF  VDC_V: 50V  [0603]  (hidden comment: 885012206095)
C169  VDC_V: 10V  ValueDisplayed: 4.7uF  [0603]  (hidden comment: GRM188R61A475MAAJ)
C171  Cap_F: 100nF  VDC_V: 50V  [0603]  (hidden comment: 885012206095)
C172  Cap_F: 1µF  VDC_V: 16V  [0603]  (hidden comment: 885012206052)
C173  VDC_V: 10V  ValueDisplayed: 10uF  [0603]  (hidden comment: C1608X5R1A106M080AC)
C174  VDC_V: 10V  ValueDisplayed: 47µF  [0805_HV]  (hidden comment: GRM21BR61A476ME15L)
C175  VDC_V: 10V  ValueDisplayed: 47µF  [0805_HV]  (hidden comment: GRM21BR61A476ME15L)
C176  Cap_F: 100nF  VDC_V: 50V  [0603]  (hidden comment: 885012206095)
C177  VDC_V: 10V  ValueDisplayed: 47µF  [0805_HV]  (hidden comment: GRM21BR61A476ME15L)
C178  VDC_V: 10V  ValueDisplayed: 47µF  [0805_HV]  (hidden comment: GRM21BR61A476ME15L)
C179  VDC_V: 25V  ValueDisplayed: 0.1uF  [0402]  (hidden comment: GRM155R61E104KA87D)
C180  VDC_V: 25V  ValueDisplayed: 0.1uF  [0402]  (hidden comment: GRM155R61E104KA87D)
C181  VDC_V: 10V  ValueDisplayed: 10uF  [0603]  (hidden comment: C1608X5R1A106M080AC)
C182  VDC_V: 50V  ValueDisplayed: 2700pF  [0402]  (hidden comment: GRM155R71H272KA01D)
C183  Cap_F: 100nF  VDC_V: 50V  [0603]  (hidden comment: 885012206095)
C184  VDC_V: 10V  ValueDisplayed: 4.7uF  [0603]  (hidden comment: GRM188R61A475MAAJ)
C185  VDC_V: 25V  ValueDisplayed: 470pF  [0402]  (hidden comment: GRM1555C1E471JA01D)
C186  VDC_V: 50V  ValueDisplayed: 2700pF  [0402]  (hidden comment: GRM155R71H272KA01D)
C187  VDC_V: 25V  ValueDisplayed: 0.1uF  [0402]  (hidden comment: GRM155R61E104KA87D)
C189  Cap_F: 100nF  VDC_V: 50V  [0603]  (hidden comment: 885012206095)
C190  VDC_V: 10V  ValueDisplayed: 10uF  [0603]  (hidden comment: C1608X5R1A106M080AC)
C191  VDC_V: 25V  ValueDisplayed: 0.1uF  [0402]  (hidden comment: GRM155R61E104KA87D)
C192  VDC_V: 10V  ValueDisplayed: 47µF  [0805_HV]  (hidden comment: GRM21BR61A476ME15L)
C193  VDC_V: 10V  ValueDisplayed: 47µF  [0805_HV]  (hidden comment: GRM21BR61A476ME15L)
C194  Cap_F: 100nF  VDC_V: 50V  [0603]  (hidden comment: 885012206095)
C195  VDC_V: 10V  ValueDisplayed: 47µF  [0805_HV]  (hidden comment: GRM21BR61A476ME15L)
C196  VDC_V: 10V  ValueDisplayed: 47µF  [0805_HV]  (hidden comment: GRM21BR61A476ME15L)
C197  VDC_V: 25V  ValueDisplayed: 0.1uF  [0402]  (hidden comment: GRM155R61E104KA87D)
C198  VDC_V: 50V  ValueDisplayed: 2700pF  [0402]  (hidden comment: GRM155R71H272KA01D)
C199  VDC_V: 10V  ValueDisplayed: 10uF  [0603]  (hidden comment: C1608X5R1A106M080AC)
C200  VDC_V: 25V  ValueDisplayed: 0.1uF  [0402]  (hidden comment: GRM155R61E104KA87D)
C201  Cap_F: 1µF  VDC_V: 16V  [0603]  (hidden comment: 885012206052)
C202  VDC_V: 25V  ValueDisplayed: 0.1uF  [0402]  (hidden comment: GRM155R61E104KA87D)
C203  VDC_V: 10V  ValueDisplayed: 10uF  [0603]  (hidden comment: C1608X5R1A106M080AC)
C204  Cap_F: 100nF  VDC_V: 50V  [0402]  (hidden comment: GRM155R61E104KA87D)
C205  VDC_V: 25V  ValueDisplayed: 0.1uF  [0402]  (hidden comment: GRM155R61E104KA87D)
C206  VDC_V: 50V  ValueDisplayed: 1800pF  [0402]  (hidden comment: GRM155R71H182KA01D)
C207  VDC_V: 25V  ValueDisplayed: 0.1uF  [0402]  (hidden comment: GRM155R61E104KA87D)
D7  value Red  [HSMx-C191_Red]  (hidden comment: HSMC-C191)
D14  value Red  [HSMx-C191_Red]  (hidden comment: HSMC-C191)
D15  value Red  [HSMx-C191_Red]  (hidden comment: HSMC-C191)
D16  value Red  [HSMx-C191_Red]  (hidden comment: HSMC-C191)
L22  ValueDisplayed: 30 ohm  [0603]  (hidden comment: 742792609)
L23  ValueDisplayed: 2.2uH  [VLCF4020]  (hidden comment: VLCF4020T-2R2N1R7)
L25  BLM18SG221TN1D  [0603]
L26  ValueDisplayed: 2.2uH  [WE-TPC_6823]  (hidden comment: 744062002)
L27  BLM18SG221TN1D  [0603]
R9  ValueDisplayed: 84.5k  [0402]  (hidden comment: CRCW040284K5FKED)
R62  ValueDisplayed: 84.5k  [0402]  (hidden comment: CRCW040284K5FKED)
R63  ValueDisplayed: 84.5k  [0402]  (hidden comment: CRCW040284K5FKED)
R153  ValueDisplayed: 0  [0805_HV]  (hidden comment: RC0805JR-070RL)
R154  ValueDisplayed: 0  [0805_HV]  (hidden comment: RC0805JR-070RL)
R160  ValueDisplayed: 523  [0402]  (hidden comment: CRCW0402523RFKED)
R161  ValueDisplayed: 0  [0201]  (hidden comment: CRCW02010000Z0ED)
R162  ValueDisplayed: 0  [0201]  (hidden comment: CRCW02010000Z0ED)
R163  ValueDisplayed: 0  [0805_HV]  (hidden comment: RC0805JR-070RL)
R164  ValueDisplayed: 1.00k  [0402]  (hidden comment: CRCW04021K00FKED)
R165  ValueDisplayed: 17.8k  [0402]  (hidden comment: CRCW040217K8FKED)
R166  ValueDisplayed: 2.49k  [0402]  (hidden comment: CRCW04022K49FKED)
R167  ValueDisplayed: 84.5k  [0402]  (hidden comment: CRCW040284K5FKED)
R168  ValueDisplayed: 10.0k  [0201]  (hidden comment: RC0201FS-7D10KL)
R169  ValueDisplayed: 383k  [0402]  (hidden comment: CRCW0402383KFKED)
R170  ValueDisplayed: 12.7k  [0402]  (hidden comment: CRCW040212K7FKED)
R171  ValueDisplayed: 330  [0402]  (hidden comment: CRCW0402160RJNED)
R172  ValueDisplayed: 523  [0402]  (hidden comment: CRCW0402523RFKED)
R173  ValueDisplayed: 0  [0201]  (hidden comment: CRCW02010000Z0ED)
R174  ValueDisplayed: 0  [0201]  (hidden comment: CRCW02010000Z0ED)
R175  ValueDisplayed: 0  [0805_HV]  (hidden comment: RC0805JR-070RL)
R176  ValueDisplayed: 2.74k  [0402]  (hidden comment: CRCW04022K74FKED)
R177  ValueDisplayed: 7.50k  [0201]  (hidden comment: RC0201FR-077K5L)
R179  ValueDisplayed: 2.21k  [0402]  (hidden comment: CRCW04022K21FKED)
R180  ValueDisplayed: 10.0k  [0201]  (hidden comment: RC0201FS-7D10KL)
R181  ValueDisplayed: 383k  [0201]  (hidden comment: RC0201FR-07383KL)
R182  ValueDisplayed: 4.99k  [0402]  (hidden comment: CRCW04024K99FKED)
R183  ValueDisplayed: 220  [0402]  (hidden comment: CRCW0402150RJNED)
R184  ValueDisplayed: 10.0k  [0201]  (hidden comment: RC0201FS-7D10KL)
R185  ValueDisplayed: 12.0k  [0402]  (hidden comment: CRCW040212K0FKED)
R186  ValueDisplayed: 0  [0201]  (hidden comment: CRCW02010000Z0ED)
R187  ValueDisplayed: 0  [0201]  (hidden comment: CRCW02010000Z0ED)
U9  LM3880MF-1AA  [DBV0006A_N]
U25  TPS54218RTER  [RTE0016F]
U26  TPS7A9601DSCR  [DRC0010J-MFG]
U27  TPS54318RTER  [RTE0016F]
U28  TPS74401RGWR  [RGW0020A]

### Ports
RX_PG_1V2 (out), RX_PG_1V8 (out), SYNC_1V2_RX (in), SYNC_1V8_RX (in)

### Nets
1V2_DVDD: C204.1 L27.2
1V8_DVDD: C25.1 C183.1 L22.2
+5.3V: C201.1 U28.10(BIAS)
AVDD_1P2: C191.1 L25.2
GND: C16.2 C24.2 C25.2 C169.2 C172.2 C173.2 C174.2 C175.2 C176.2 C177.2 C178.2 C179.2 C180.2 C181.2 C182.2 C183.2 C184.2 C185.2 C186.2 C187.2 C190.2 C191.2 C192.2 C193.2 C194.2 C195.2 C196.2 C197.2 C198.2 C199.2 C200.2 C201.2 C202.2 C203.2 C204.2 C205.2 C206.2 C207.2 R168.1 R169.2 R170.1 R180.1 R181.2 R182.1 R184.1 R185.1 U9.2(GND) U25.3(GND) U25.4(GND) U25.5(AGND) U25.17(PAD) U26.6(GND) U26.11(Thermal_Pad) U27.3(GND) U27.4(GND) U27.5(AGND) U27.17(PAD) U28.12(GND) U28.21(GND)
VBUS: C16.1 R9.2 R62.2 R63.2 R163.1 R164.2 R175.1 R176.2 U9.1(VCC)
1.8V_EN: R9.1 R166.1 R184.2 U9.6(FLAG1) U26.3(EN_UV)
1.15V_EN: R62.1 U9.5(FLAG2) U28.11(EN)
GLOBAL ENABLE: R161.1 R173.1 ; off-sheet GLOBAL ENABLE
RX_PG_1V2: D14.2(K) U27.14(PWRGD) ; port RX_PG_1V2
RX_PG_1V8: D7.2(K) U25.14(PWRGD) ; port RX_PG_1V8
SYNC_1V2_RX: R187.2 ; port SYNC_1V2_RX
SYNC_1V8_RX: R186.2 ; port SYNC_1V8_RX
NetC24_1: C24.1 U9.3(EN)
NetC169_1: C169.1 C180.1 C181.1 L22.1 R153.2 R167.2 U26.8(SNS) U26.9(OUT) U26.10(OUT)
NetC171_1: C171.1 L23.1 U25.10(PH) U25.11(PH) U25.12(PH)
NetC171_2: C171.2 U25.13(BOOT)
NetC172_1: C172.1 C173.1 C177.1 C178.1 C179.1 L23.2 R153.1 R165.2 R166.2 U26.1(IN) U26.2(IN)
NetC174_1: C174.1 C175.1 C176.1 R160.1 R162.1 R163.2 U25.1(VIN) U25.2(VIN) U25.16(VIN)
NetC182_1: C182.1 U25.9(SS)
NetC184_1: C184.1 R185.2 U26.7(NR/SS)
NetC185_1: C185.1 R167.1 R170.2 U26.5(FB_PG)
NetC186_1: C186.1 R171.2 U25.7(COMP)
NetC187_1: C187.1 R171.1
NetC189_1: C189.1 L26.1 U27.10(PH) U27.11(PH) U27.12(PH)
NetC189_2: C189.2 U27.13(BOOT)
NetC190_1: C190.1 C202.1 C203.1 L25.1 L27.1 R154.2 R179.2 U28.1(OUT) U28.18(OUT) U28.19(OUT) U28.20(OUT)
NetC192_1: C192.1 C193.1 C194.1 R172.1 R174.1 R175.2 U27.1(VIN) U27.2(VIN) U27.16(VIN)
NetC195_1: C195.1 C196.1 C197.1 C199.1 C200.1 L26.2 R154.1 R177.2 U28.5(IN) U28.6(IN) U28.7(IN) U28.8(IN)
NetC198_1: C198.1 U27.9(SS)
NetC205_1: C205.1 U28.15(SS)
NetC206_1: C206.1 R183.2 U27.7(COMP)
NetC207_1: C207.1 R183.1
NetD7_1: D7.1(A) R160.2
NetD14_1: D14.1(A) R172.2
NetD15_1: D15.1(A) R176.1
NetD15_2: D15.2(K) U28.9(PG)
NetD16_1: D16.1(A) R164.1
NetD16_2: D16.2(K) U26.4(PG)
NetR63_1: R63.1 U9.4(FLAG3)
NetR161_2: R161.2 R162.2 U25.15(EN)
NetR165_1: R165.1 R168.2 U25.6(VSENSE)
NetR169_1: R169.1 R186.1 U25.8(RT/CLK)
NetR173_2: R173.2 R174.2 U27.15(EN)
NetR177_1: R177.1 R180.2 U27.6(VSENSE)
NetR179_1: R179.1 R182.2 U28.16(FB/SNS)
NetR181_1: R181.1 R187.1 U27.8(RT/CLK)

Not connected (* = marked no-connect by the designer): U28 2(NC)* 3(NC)* 4(NC)* 13(NC)* 14(NC)* 17(NC)*

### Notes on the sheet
- 1.8V: 300mA for Tx +500mA for Rx
- (near R164) 1.8V: 300mA for Tx +500mA for Rx. maximum drop:0.35V
- 1.8V has to be applied before 1.1V supply
- (near L23) Isat=1.72A
- 2.232V
- min:2.182V
- input range: 1.9V~5.7V
- 1.8V for Tx PS
- (near R166) Vin>2.1233V
- 2.232V to 1.8V @ 2A LDO for Tx/Rx Supply
- VFB=0.803V typ
- 2 V @ 1 A RX Supply
- VBUS range: 3.0V~5.5V
- 1.15V: 1.9A for Rx
- (near L26) Isat=2.7A
- (near R177) Vo=1.405V
- (near U28) maximum IPG is 1.5mA according datasheet
- (near R179) Vo=1.154 typ
- VFB=0.803V
- VFB=0.8V typ
- 1.15V 4A LDO for RX: 1.15V PS

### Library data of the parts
C16 C24 C179 C180 C187 C191 C197 C200 C202 C205 C207 = CMP-0006607-1: as C68 on sheet Sht04--FPGA Power Supply
C25 C171 C176 C183 C189 C194 = CMP-0006837-2: as C56 on sheet Sht04--FPGA Power Supply
C169 C184 = CMP-0007329-4: CAP, CERM, 4.7 uF, 10 V, +/- 20%, X5R, 0603; Manufacturer: MuRata; TaMin_C: -55°C; Polarized: N; SizeAreaWB_mm2: 4.68; Value1: Unknown; U/M: EA; Value: 4.7uF; TaMax_C: 85°C; SizeZ_mm: 1; SizeX_mm: 1.6; SizeY_mm: 0.8; SizeArea_mm2: 1.28; Cap_F: 4.7µF; AEC Category: Q200
C172 = CMP-0006831-1: CAP, CERM, 1 uF, 16 V, +/- 10%, X7R, 0603; Manufacturer: Wurth Elektronik; TaMin_C: -55°C; Polarized: N; SizeAreaWB_mm2: 4.68; Value1: Unknown; U/M: EA; Value: 1uF; TaMax_C: 125°C; SizeZ_mm: 1; SizeX_mm: 1.6; SizeY_mm: 0.8; SizeArea_mm2: 1.28; AEC Category: Q200
C173 C181 C190 C199 C203 = CMP-0007003-5: CAP, CERM, 10 uF, 10 V, +/- 20%, X5R, 0603; Manufacturer: TDK; TaMin_C: -55°C; ESR_ohm: 7.8m; Polarized: N; SizeAreaWB_mm2: 4.68; Value1: 0.0078 ohm; U/M: EA; Value: 10uF; TaMax_C: 85°C; SizeZ_mm: 1; SizeX_mm: 1.6; SizeY_mm: 0.8; SizeArea_mm2: 1.28; Cap_F: 10µF; IRMS_A: 1.85A; AEC Category: Q200
C174 C175 C177 C178 C192 C193 C195 C196 = CMP-0078699-1: as C58 on sheet Sht04--FPGA Power Supply
C182 C186 C198 = CMP-0006686-1: as C62 on sheet Sht04--FPGA Power Supply
C185 = CMP-0006389-2: CAP, CERM, 470 pF, 25 V, +/- 5%, C0G/NP0, 0402; Manufacturer: MuRata; TaMin_C: -55°C; Polarized: N; SizeAreaWB_mm2: 3; Value1: Unknown; U/M: EA; Value: 470pF; TaMax_C: 125°C; SizeZ_mm: 0.6; SizeX_mm: 1; SizeY_mm: 0.5; AEC Category: Q200
C201 = CMP-0006831-4: CAP, CERM, 1 uF, 16 V, +/- 10%, X7R, 0603; Manufacturer: Wurth Elektronik; TaMin_C: -55°C; Polarized: N; SizeAreaWB_mm2: 4.68; Value1: Unknown; U/M: EA; Value: 1uF; TaMax_C: 125°C; SizeZ_mm: 1; SizeX_mm: 1.6; SizeY_mm: 0.8; SizeArea_mm2: 1.28; AEC Category: Q200
C204 = CMP-0006837-2: as C86 on sheet Sht04--FPGA Power Supply
C206 = CMP-0006680-2: CAP, CERM, 1800 pF, 50 V, +/- 10%, X7R, 0402; Manufacturer: MuRata; TaMin_C: -55°C; Polarized: N; SizeAreaWB_mm2: 3; Value1: Unknown; U/M: EA; Value: 1800pF; TaMax_C: 125°C; SizeZ_mm: 0.6; SizeX_mm: 1; SizeY_mm: 0.5; Cap_F: 1.8nF; AEC Category: Q200
D7 D14-D16 = CMP-0078541-2: as D4 on sheet Sht04--FPGA Power Supply
L22 = 742792609: Ferrite Bead, 30 ohm @ 100 MHz, 3 A, 0603; Manufacturer: Wurth Elektronik; Value: 30 ohm; Imax_A: 3; DCR_ohm: 0.04; Value1: 0.04 ohm; Value2: 3A; SizeAreaWB_mm2: 4.68; SizeArea_mm2: 1.28; SizeX_mm: 1.6; SizeY_mm: 0.8; SizeZ_mm: 1; ZTyp@100MHz_Ohm: 30; Ztyp@1GHz_Ohm: 40.472; Green_Lifecycle: Active; Green_REACh: Passed
L23 = CMP-0062895-1: Inductor, Shielded, Ferrite, 2.2 uH, 1.72 A, 0.059 ohm, SMD; Manufacturer: TDK; Isat: 1.72A @ 30% inductance drop; Irms: 2.19A @ 40C rise; Green_Lifecycle: Active; SizeAreaWB_mm2: 25; DCR_ohm: 59m; Green_REACh: Passed; Value: 2.2uH; Imax_A: 1.72A; SizeZ_mm: 2; SizeX_mm: 4; SizeArea_mm2: 16; Ind_H: 2.2µH; AEC Category: Q200
L25 L27 = CMP-0003353-1: as L11 on sheet Sht04--FPGA Power Supply
L26 = CMP-0063839-1: Inductor, Shielded Drum Core, Metal Composite, 2.2 uH, 2.7 A, 0.017 ohm, SMD; Manufacturer: Wurth Elektronik; Isat: 2.7A @ 35% inductance drop; Irms: 3.4A @ 30C rise; Green_Lifecycle: Active; SizeAreaWB_mm2: 77.44; DCR_ohm: 17m; Green_REACh: Passed; Value: 2.2uH; Imax_A: 2.7A; SizeZ_mm: 2.5; SizeX_mm: 6.8; SizeArea_mm2: 46.24; Ind_H: 2.2µH; AEC Category: Q200
R9 R62 R63 R167 = CMP-0026578-2: RES, 84.5 k, 1%, 0.063 W, AEC-Q200 Grade 0, 0402; Manufacturer: Vishay-Dale; Power_W: 63mW; TempCo: 100 ppm/C; Value_Code: 84k5; Value: 84.5k; EIA_Code: E96; SizeX_mm: 1; SizeY_mm: 0.5; SizeZ_mm: 0.6; Value2: 0.063W; AEC Qualified: Y; VDC_V: 50V; AEC Category: Q200; AEC Grade: 0
R153 R154 R163 R175 = CMP-0020803-2: as R67 on sheet Sht04--FPGA Power Supply
R160 R172 = CMP-0026440-2: as R64 on sheet Sht04--FPGA Power Supply
R161 R162 R173 R174 R186 R187 = CMP-0027008-1: as R189-R191 on sheet Sht04--FPGA Power Supply
R164 = CMP-0026071-3: RES, 1.00 k, 1%, 0.063 W, AEC-Q200 Grade 0, 0402; Manufacturer: Vishay-Dale; Power_W: 63mW; TempCo: 100 ppm/C; Value_Code: 1k00; Value: 1.00k; EIA_Code: E96; Res_ohm: 1k; SizeX_mm: 1; SizeY_mm: 0.5; SizeZ_mm: 0.6; Value2: 0.063W; AEC Qualified: Y; VDC_V: 50V; AEC Category: Q200; AEC Grade: 0
R165 = CMP-0026051-3: RES, 17.8 k, 1%, 0.063 W, AEC-Q200 Grade 0, 0402; Manufacturer: Vishay-Dale; Power_W: 63mW; TempCo: 100 ppm/C; Value_Code: 17k8; Value: 17.8k; EIA_Code: E96; SizeX_mm: 1; SizeY_mm: 0.5; SizeZ_mm: 0.6; Value2: 0.063W; AEC Qualified: Y; VDC_V: 50V; AEC Category: Q200; AEC Grade: 0
R166 = CMP-0026237-2: RES, 2.49 k, 1%, 0.063 W, AEC-Q200 Grade 0, 0402; Manufacturer: Vishay-Dale; Power_W: 63mW; TempCo: 100 ppm/C; Value_Code: 2k49; Value: 2.49k; EIA_Code: E96; SizeX_mm: 1; SizeY_mm: 0.5; SizeZ_mm: 0.6; Value2: 0.063W; AEC Qualified: Y; VDC_V: 50V; AEC Category: Q200; AEC Grade: 0
R168 R180 R184 = CMP-0028071-1: as R72-R74 on sheet Sht04--FPGA Power Supply
R169 = CMP-0026321-2: RES, 383 k, 1%, 0.063 W, AEC-Q200 Grade 0, 0402; Manufacturer: Vishay-Dale; Power_W: 63mW; TempCo: 100 ppm/C; Value: 383k; EIA_Code: E96; SizeX_mm: 1; SizeY_mm: 0.5; SizeZ_mm: 0.6; Value2: 0.063W; AEC Qualified: Y; VDC_V: 50V; AEC Category: Q200; AEC Grade: 0
R170 = CMP-0025993-3: RES, 12.7 k, 1%, 0.063 W, AEC-Q200 Grade 0, 0402; Manufacturer: Vishay-Dale; Power_W: 63mW; TempCo: 100 ppm/C; Value_Code: 12k7; Value: 12.7k; EIA_Code: E96; SizeX_mm: 1; SizeY_mm: 0.5; SizeZ_mm: 0.6; Value2: 0.063W; AEC Qualified: Y; VDC_V: 50V; AEC Category: Q200; AEC Grade: 0
R171 = CMP-0026845-3: as R76 on sheet Sht04--FPGA Power Supply
R176 = CMP-0026241-2: RES, 2.74 k, 1%, 0.063 W, AEC-Q200 Grade 0, 0402; Manufacturer: Vishay-Dale; Power_W: 63mW; TempCo: 100 ppm/C; Value_Code: 2k74; Value: 2.74k; EIA_Code: E96; SizeX_mm: 1; SizeY_mm: 0.5; SizeZ_mm: 0.6; Value2: 0.063W; AEC Qualified: Y; VDC_V: 50V; AEC Category: Q200; AEC Grade: 0
R177 = CMP-0027878-1: RES, 7.50 k, 1%, 0.05 W, 0201; Manufacturer: Yageo America; Power_W: 50mW; TempCo: 200 ppm/C; Value_Code: 7k50; U/M: EA; Value: 7.50k; EIA_Code: E96; Res_ohm: 7.5k; SizeX_mm: 0.6; SizeY_mm: 0.3; SizeZ_mm: 0.26; Value2: 0.05W; SizeArea_mm2: 0.18; AEC Qualified: N; VDC_V: 25V; AEC Category: Q200
R179 = CMP-0026232-2: RES, 2.21 k, 1%, 0.063 W, AEC-Q200 Grade 0, 0402; Manufacturer: Vishay-Dale; Power_W: 63mW; TempCo: 100 ppm/C; Value_Code: 2k21; Value: 2.21k; EIA_Code: E96; SizeX_mm: 1; SizeY_mm: 0.5; SizeZ_mm: 0.6; Value2: 0.063W; AEC Qualified: Y; VDC_V: 50V; AEC Category: Q200; AEC Grade: 0
R181 = CMP-0027640-1: as R75 on sheet Sht04--FPGA Power Supply
R182 = CMP-0026414-2: RES, 4.99 k, 1%, 0.063 W, AEC-Q200 Grade 0, 0402; Manufacturer: Vishay-Dale; Power_W: 63mW; TempCo: 100 ppm/C; Value_Code: 4k99; Value: 4.99k; EIA_Code: E96; SizeX_mm: 1; SizeY_mm: 0.5; SizeZ_mm: 0.6; Value2: 0.063W; AEC Qualified: Y; VDC_V: 50V; AEC Category: Q200; AEC Grade: 0
R183 = CMP-0026841-3: RES, 150, 5%, 0.063 W, AEC-Q200 Grade 0, 0402; Manufacturer: Panasonic Electronic Components; PartNumber: ERJ-2RKF2200X; Power_W: 63mW; TempCo: 200 ppm/C; Value_Code: 220R; Value1: 1%; Value: 220; EIA_Code: E24; SizeX_mm: 1; SizeY_mm: 0.5; SizeZ_mm: 0.6; Value2: 0.063W; AEC Qualified: Y; VDC_V: 50V; AEC Category: Q200; AEC Grade: 0
R185 = CMP-0025990-3: RES, 12.0 k, 1%, 0.063 W, AEC-Q200 Grade 0, 0402; Manufacturer: Vishay-Dale; Power_W: 63mW; TempCo: 100 ppm/C; Value_Code: 12k0; Value: 12.0k; Res_ohm: 12k; SizeX_mm: 1; SizeY_mm: 0.5; SizeZ_mm: 0.6; Value2: 0.063W; AEC Qualified: Y; VDC_V: 50V; AEC Grade: 0; AEC Category: Q200
U9 = CMP-0071684-1: Power Sequencer, 6-pin SOT-23, 1000 Reel; Manufacturer: Texas Instruments; CompType: MiscPower; PackageTopMarking: F20A*XTT; High-Reliability: Y; PowerWise: N
U25 = CMP-0073970-3: as U11 on sheet Sht04--FPGA Power Supply
U26 = CMP-0096730-1: 2-A, Ultra-low Noise, Ultra-high PSRR, RF Voltage Regulator; Manufacturer: Texas Instruments; Output Type: AdjustableProgrammable; TJmax_C: +125°C; Min Supply Voltage: 1.7V; Max Supply Voltage: 5.7V; Output Voltage: 0.4-5.5V; Dropout Voltage: 215mV; Standoff Height: 0mm; AEC Qualified: No; SizeZ_mm: 1mm; Accuracy Percentage: 1%; Number Of Outputs: 1; Nominal Supply Current: 15-49mA
U27 = CMP-0860372-1: 2.95V to 6V Input, 3A Synchronous Step-Down SWIFT™ Converter, RTE0016F (WQFN-16); Alternate PartNumber: TPS54318RTET; Manufacturer: Texas Instruments; SizeAreaWB_mm2: 16; SizeZ_mm: 0.8; SizeArea_mm2: 9; Rating: Catalog; AEC Qualified: N; CompType: IC; SizeX_mm: 3; AEC Category: Q200
U28 = CMP-0036360-4: Single-Output LDO, 3A, Adj (0.8V to 3.3V), Fast Transient Response, Programmable Soft Start, RGW0020A (VQFN-20); Manufacturer: Texas Instruments; SizeAreaWB_mm2: 49.0; Vin(Min)(V): 0.8; SizeArea_mm2: 25.0; Green_REACh: Passed; Vout Adj(Max)(V): 3.6; CompType: IC; SizeY_mm: 5.0; Green_Lifecycle: Active; AEC Qualified: N; Rating: Catalog; SizeZ_mm: 1.0; Iout(Max)(A): 3; AEC Category: Q200; Vin(Max)(V): 5.5; Power Good: TRUE; Vdo(Typ)(mV): 115; Accuracy(%): 1

## Sheet Sht06--TX Supply +5V and -5V.SchDoc: LVPS RX Supply +5V & -5V
size 431 x 279 mm; Date: Not shown in title block; ApprovedBy: Not shown in title block; CheckedBy: Not shown in title block; Author: Not shown in title block; CompanyName: Not shown in title block; DrawnBy: Bill.Xu; Engineer: Bill.Xu; Organization: Not shown in title block; Address1: Not shown in title block; Address2: Not shown in title block; Address3: Not shown in title block; Address4: Not shown in title block; DocumentNumber: 1; Revision: Use project parameter SCH_Rev; SheetNumber: 6; SheetTotal: 7; PageSetup: Record=PageOptions¦CenterHorizontal=True¦CenterVertical=True¦PrintScale=1.00¦XCorrection=1.00¦YCorrection=1.00¦PrintKind=0¦BorderSize=5000000¦LeftOffset=0¦BottomOffset=0¦Orientation=2¦PaperLength=1000¦PaperWidth=1000¦Scale=100¦PaperSource=15¦PrintQuality=600¦MediaType=1¦DitherType=10¦PaperKind=Letter¦PrintScaleMode=1
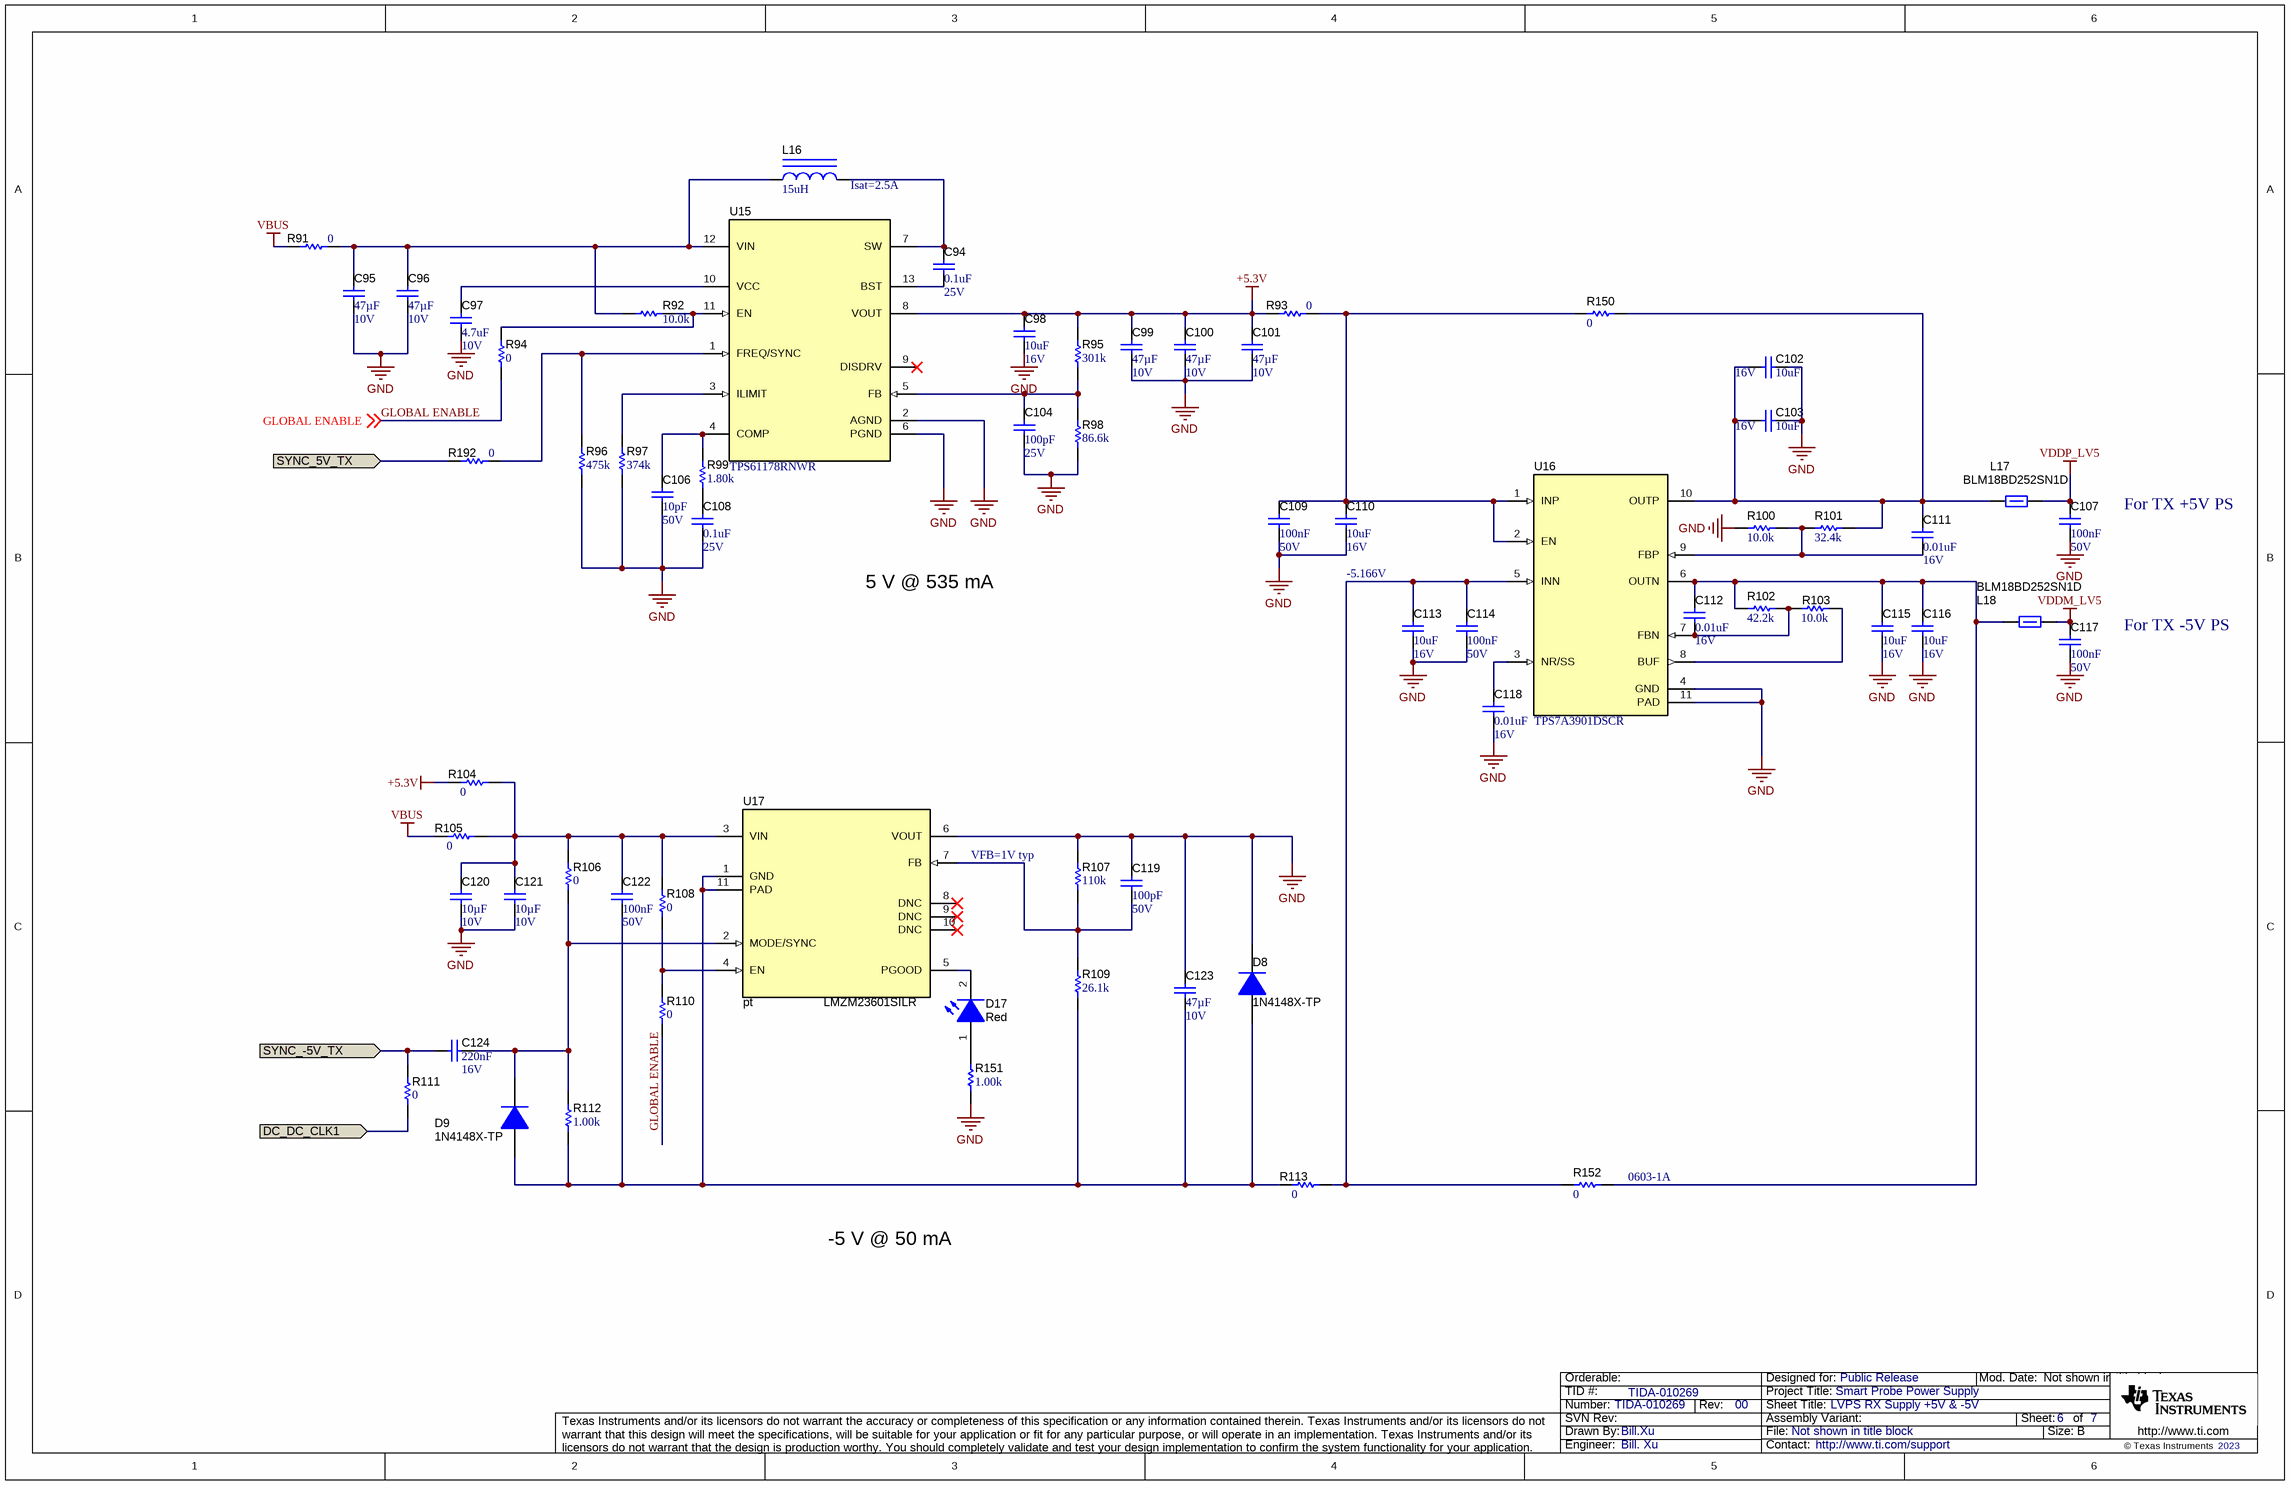
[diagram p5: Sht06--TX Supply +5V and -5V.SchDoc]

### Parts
C94  VDC_V: 25V  ValueDisplayed: 0.1uF  [0402]  (hidden comment: GRM155R61E104KA87D)
C95  VDC_V: 10V  ValueDisplayed: 47µF  [0805_HV]  (hidden comment: GRM21BR61A476ME15L)
C96  VDC_V: 10V  ValueDisplayed: 47µF  [0805_HV]  (hidden comment: GRM21BR61A476ME15L)
C97  VDC_V: 10V  ValueDisplayed: 4.7uF  [0603]  (hidden comment: GRM188R61A475MAAJ)
C98  VDC_V: 16V  ValueDisplayed: 10uF  [0603]  (hidden comment: GRM188R61C106MAALD)
C99  VDC_V: 10V  ValueDisplayed: 47µF  [0805_HV]  (hidden comment: GRM21BR61A476ME15L)
C100  VDC_V: 10V  ValueDisplayed: 47µF  [0805_HV]  (hidden comment: GRM21BR61A476ME15L)
C101  VDC_V: 10V  ValueDisplayed: 47µF  [0805_HV]  (hidden comment: GRM21BR61A476ME15L)
C102  VDC_V: 16V  ValueDisplayed: 10uF  [0603]  (hidden comment: GRM188R61C106MAALD)
C103  VDC_V: 16V  ValueDisplayed: 10uF  [0603]  (hidden comment: GRM188R61C106MAALD)
C104  VDC_V: 25V  ValueDisplayed: 100pF  [0201_033]  (hidden comment: GRM033R71E101JA01D)
C106  VDC_V: 50V  ValueDisplayed: 10pF  [0402]  (hidden comment: GRM1555C1H100FA01D)
C107  Cap_F: 100nF  VDC_V: 50V  [0603]  (hidden comment: 885012206095)
C108  VDC_V: 25V  ValueDisplayed: 0.1uF  [0402]  (hidden comment: GRM155R61E104KA87D)
C109  Cap_F: 100nF  VDC_V: 50V  [0603]  (hidden comment: 885012206095)
C110  VDC_V: 16V  ValueDisplayed: 10uF  [0603]  (hidden comment: GRM188R61C106MAALD)
C111  VDC_V: 16V  ValueDisplayed: 0.01uF  [0402]  (hidden comment: 885012205031)
C112  VDC_V: 16V  ValueDisplayed: 0.01uF  [0402]  (hidden comment: 885012205031)
C113  VDC_V: 16V  ValueDisplayed: 10uF  [0603]  (hidden comment: GRM188R61C106MAALD)
C114  Cap_F: 100nF  VDC_V: 50V  [0603]  (hidden comment: 885012206095)
C115  VDC_V: 16V  ValueDisplayed: 10uF  [0603]  (hidden comment: GRM188R61C106MAALD)
C116  VDC_V: 16V  ValueDisplayed: 10uF  [0603]  (hidden comment: GRM188R61C106MAALD)
C117  Cap_F: 100nF  VDC_V: 50V  [0603]  (hidden comment: 885012206095)
C118  VDC_V: 16V  ValueDisplayed: 0.01uF  [0402]  (hidden comment: 885012205031)
C119  VDC_V: 50V  ValueDisplayed: 100pF  [0402]  (hidden comment: 885012005061)
C120  Cap_F: 10µF  VDC_V: 10V  [0805_HV]  (hidden comment: 885012207026)
C121  Cap_F: 10µF  VDC_V: 10V  [0805_HV]  (hidden comment: 885012207026)
C122  Cap_F: 100nF  VDC_V: 50V  [0603]  (hidden comment: 885012206095)
C123  VDC_V: 10V  ValueDisplayed: 47µF  [0805_HV]  (hidden comment: GRM21BR61A476ME15L)
C124  Cap_F: 220nF  VDC_V: 16V  [0603]  (hidden comment: 885012206048)
D8  1N4148X-TP  [SOD-523]
D9  1N4148X-TP  [SOD-523]
D17  value Red  [HSMx-C191_Red]  (hidden comment: HSMC-C191)
L16  ValueDisplayed: 15uH  [IHLP-2020CZ]  (hidden comment: IHLP2020CZER150M01)
L17  BLM18BD252SN1D  [0603]
L18  BLM18BD252SN1D  [0603]
R91  ValueDisplayed: 0  [0805_HV]  (hidden comment: RC0805JR-070RL)
R92  ValueDisplayed: 10.0k  [0201]  (hidden comment: RC0201FR-7D10KL)
R93  ValueDisplayed: 0  [0603]  (hidden comment: RC0603JR-070RL)
R94  ValueDisplayed: 0  [0201]  (hidden comment: CRCW02010000Z0ED)
R95  ValueDisplayed: 301k  [0201]  (hidden comment: RC0201FS-7D301KL)
R96  ValueDisplayed: 475k  [0201]  (hidden comment: RC0201FR-07475KL)
R97  ValueDisplayed: 374k  [0201]  (hidden comment: RC0201FR-07374KL)
R98  ValueDisplayed: 86.6k  [0201]  (hidden comment: RC0201FR-0786K6L)
R99  ValueDisplayed: 1.80k  [0201]  (hidden comment: RC0201FR-071K8L)
R100  ValueDisplayed: 10.0k  [0201]  (hidden comment: RC0201FR-7D10KL)
R101  ValueDisplayed: 32.4k  [0201]  (hidden comment: RC0201FR-0732K4L)
R102  ValueDisplayed: 42.2k  [0201]  (hidden comment: RC0201FR-0742K2L)
R103  ValueDisplayed: 10.0k  [0201]  (hidden comment: RC0201FR-7D10KL)
R104  ValueDisplayed: 0  [0603]  (hidden comment: RC0603JR-070RL)
R105  ValueDisplayed: 0  [0603]  (hidden comment: RC0603JR-070RL)
R106  ValueDisplayed: 0  [0201]  (hidden comment: CRCW02010000Z0ED)
R107  ValueDisplayed: 110k  [0402]  (hidden comment: CRCW0402110KJNED)
R108  ValueDisplayed: 0  [0201]  (hidden comment: CRCW02010000Z0ED)
R109  ValueDisplayed: 26.1k  [0201]  (hidden comment: RC0201FR-0726K1L)
R110  ValueDisplayed: 0  [0201]  (hidden comment: CRCW02010000Z0ED)
R111  ValueDisplayed: 0  [0201]  (hidden comment: CRCW02010000Z0ED)
R112  ValueDisplayed: 1.00k  [0402]  (hidden comment: RC0402FR-071KL)
R113  ValueDisplayed: 0  [0603]  (hidden comment: RC0603JR-070RL)
R150  ValueDisplayed: 0  [0603]  (hidden comment: RC0603JR-070RL)
R151  ValueDisplayed: 1.00k  [0402]  (hidden comment: CRCW04021K00FKED)
R152  ValueDisplayed: 0  [0603]  (hidden comment: RC0603JR-070RL)
R192  ValueDisplayed: 0  [0201]  (hidden comment: CRCW02010000Z0ED)
U15  TPS61178RNWR  [RNW0013A]
U16  TPS7A3901DSCR  [DSC0010J]
U17  LMZM23601SILR  PartNumber: pt  [SIL0010A]

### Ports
DC_DC_CLK1 (in), SYNC_5V_TX (in), SYNC_-5V_TX (in)

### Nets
+5.3V: C98.1 C99.1 C100.1 C101.1 R93.1 R95.2 R104.1 U15.8(VOUT)
GND: C95.2 C96.2 C97.2 C98.2 C99.2 C100.2 C101.2 C102.2 C103.2 C104.2 C106.2 C107.2 C108.2 C109.2 C110.2 C113.2 C114.2 C115.1 C116.1 C117.2 C118.2 C119.1 C120.2 C121.2 C123.1 D8.1(K) R96.1 R97.1 R98.1 R100.1 R107.2 R151.2 U15.2(AGND) U15.6(PGND) U16.4(GND) U16.11(PAD) U17.6(VOUT)
VBUS: R91.1 R105.1
VDDM_LV5: C117.1 L18.2
VDDP_LV5: C107.1 L17.2
DC_DC_CLK1: R111.1 ; port DC_DC_CLK1
GLOBAL ENABLE: R94.1 R110.1 ; off-sheet GLOBAL ENABLE
SYNC_5V_TX: R192.1 ; port SYNC_5V_TX
SYNC_-5V_TX: C124.2 R111.2 ; port SYNC_-5V_TX
NetC94_1: C94.1 L16.2 U15.7(SW)
NetC94_2: C94.2 U15.13(BST)
NetC95_1: C95.1 C96.1 L16.1 R91.2 R92.1 U15.12(VIN)
NetC97_1: C97.1 U15.10(VCC)
NetC102_1: C102.1 C103.1 C111.1 L17.1 R101.2 R150.2 U16.10(OUTP)
NetC104_1: C104.1 R95.1 R98.2 U15.5(FB)
NetC106_1: C106.1 R99.2 U15.4(COMP)
NetC108_1: C108.1 R99.1
NetC109_1: C109.1 C110.1 R93.2 R150.1 U16.1(INP) U16.2(EN)
NetC111_2: C111.2 R100.2 R101.1 U16.9(FBP)
NetC112_1: C112.1 C115.2 C116.2 L18.1 R102.1 R152.2 U16.6(OUTN)
NetC112_2: C112.2 R102.2 R103.1 U16.7(FBN)
NetC113_1: C113.1 C114.1 R113.2 R152.1 U16.5(INN)
NetC118_1: C118.1 U16.3(NR/SS)
NetC119_2: C119.2 R107.1 R109.2 U17.7(FB)
NetC120_1: C120.1 C121.1 C122.1 R104.2 R105.2 R106.2 R108.2 U17.3(VIN)
NetC122_2: C122.2 C123.2 D8.2(A) D9.2(A) R109.1 R112.1 R113.1 U17.1(GND) U17.11(PAD)
NetC124_1: C124.1 D9.1(K) R106.1 R112.2 U17.2(MODE/SYNC)
NetD17_1: D17.1(A) R151.1
NetD17_2: D17.2(K) U17.5(PGOOD)
NetR92_2: R92.2 R94.2 U15.11(EN)
NetR96_2: R96.2 R192.2 U15.1(FREQ/SYNC)
NetR97_2: R97.2 U15.3(ILIMIT)
NetR103_2: R103.2 U16.8(BUF)
NetR108_1: R108.1 R110.2 U17.4(EN)

Not connected (* = marked no-connect by the designer): U15 9(DISDRV)*; U17 8(DNC)* 9(DNC)* 10(DNC)*

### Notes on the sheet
- (near L16) Isat=2.5A
- For TX +5V PS
- 5 V @ 535 mA
- -5.166V
- For TX -5V PS
- VFB=1V typ
- -5 V @ 50 mA
- (near R152) 0603-1A

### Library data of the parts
C94 C108 = CMP-0006607-1: as C68 on sheet Sht04--FPGA Power Supply
C95 C96 C99-C101 C123 = CMP-0078699-1: as C58 on sheet Sht04--FPGA Power Supply
C97 = CMP-0007329-4: as C169 on sheet Sht05--TX-RX Supply 1.8V and 1.15V
C98 C102 C103 C110 C113 C115 C116 = CMP-0007336-4: CAP, CERM, 10 uF, 16 V, +/- 20%, X5R, 0603; Manufacturer: MuRata; TaMin_C: -55°C; Polarized: N; SizeAreaWB_mm2: 4.68; Value1: Unknown; U/M: EA; Value: 10uF; TaMax_C: 85°C; SizeZ_mm: 1; SizeX_mm: 1.6; SizeY_mm: 0.8; SizeArea_mm2: 1.28; Cap_F: 10µF; AEC Category: Q200
C104 = CMP-0009762-1: CAP, CERM, 100 pF, 25 V, +/- 5%, C0G/NP0, 0201; Manufacturer: MuRata; TaMin_C: -55°C; Polarized: N; SizeAreaWB_mm2: 2.08; Value1: Unknown; U/M: EA; Value: 100pF; TaMax_C: 125°C; SizeZ_mm: 0.33; SizeX_mm: 0.6; SizeY_mm: 0.3; Cap_Case: 0201; SizeArea_mm2: 0.18; AEC Category: Q200
C106 = CMP-0064916-2: CAP, CERM, 10 pF, 50 V,+/- 1%, C0G/NP0, 0402; Manufacturer: MuRata; TaMin_C: -55°C; Polarized: N; SizeAreaWB_mm2: 3; Value1: Unknown; U/M: EA; Value: 10pF; TaMax_C: 125°C; SizeZ_mm: 0.6; SizeX_mm: 1; SizeY_mm: 0.5; AEC Category: Q200
C107 C109 C114 C117 C122 = CMP-0006837-2: as C56 on sheet Sht04--FPGA Power Supply
C111 C112 C118 = CMP-0006227-2: CAP, CERM, 0.01 uF, 16 V, +/- 10%, X7R, 0402; Manufacturer: Wurth Elektronik; TaMin_C: -55°C; Polarized: N; SizeAreaWB_mm2: 3; Value1: Unknown; U/M: EA; Value: 0.01uF; TaMax_C: 125°C; SizeZ_mm: 0.6; SizeX_mm: 1; SizeY_mm: 0.5; Cap_F: 10nF; AEC Category: Q200
C119 = CMP-0006217-1: CAP, CERM, 100 pF, 50 V, +/- 5%, C0G/NP0, 0402; Manufacturer: Wurth Elektronik; TaMin_C: -55°C; Polarized: N; SizeAreaWB_mm2: 3; Value1: Unknown; U/M: EA; Value: 100pF; TaMax_C: 125°C; SizeZ_mm: 0.6; SizeX_mm: 1; SizeY_mm: 0.5; AEC Category: Q200
C120 C121 = CMP-0007691-1: CAP, CERM, 10 uF, 10 V, +/- 10%, X7R, 0805; Manufacturer: Wurth Elektronik; TaMin_C: -55°C; Polarized: N; SizeAreaWB_mm2: 6.75; Value1: Unknown; U/M: EA; Value: 10uF; TaMax_C: 125°C; SizeZ_mm: 1.45; SizeX_mm: 2; SizeY_mm: 1.25; Cap_Case: 0805; SizeArea_mm2: 2.5; AEC Category: Q200
C124 = CMP-0006830-3: CAP, CERM, 0.22 uF, 16 V, +/- 10%, X7R, 0603; Manufacturer: Wurth Elektronik; TaMin_C: -55°C; Polarized: N; SizeAreaWB_mm2: 4.68; Value1: Unknown; U/M: EA; Value: 0.22uF; TaMax_C: 125°C; SizeZ_mm: 1; SizeX_mm: 1.6; SizeY_mm: 0.8; SizeArea_mm2: 1.28; AEC Category: Q200
D8 D9 = CMP-0076957-2: Diode, Switching, 75 V, 0.3 A, SOD-523; Manufacturer: Micro Commercial Components; SizeAreaWB_mm2: 5.13; Vr_V: 75V; SizeArea_mm2: 1.53; TJmax_C: 150°C; AEC Category: Q101; Value: 75V; SizeZ_mm: 0.65; Green_REACh: Incomplete; Io_A: 300mA; Vf_V: 1.25V; SizeY_mm: 0.9; Green_Lifecycle: Not Set; U/M: EA; Value1: 0.3A; SizeX_mm: 1.7
D17 = CMP-0078541-2: as D4 on sheet Sht04--FPGA Power Supply
L16 = CMP-0063603-4: Inductor, Shielded Drum Core, Powdered Iron, 15 uH, 1.9 A, 0.265 ohm, SMD; Manufacturer: Vishay-Dale; Isat: 2.5A @ 20% inductance drop; Irms: 1.9A @ 40C rise; Green_Lifecycle: Active; SizeAreaWB_mm2: 53.7782; DCR_ohm: 0.265; Green_REACh: Passed; Value: 15uH; Imax_A: 1.9A; SizeZ_mm: 3; SizeX_mm: 5.49; SizeY_mm: 5.18; SizeArea_mm2: 28.4382; Ind_H: 15µH; AEC Qualified: N; AEC Category: Q200
L17 L18 = CMP-0003346-2: Ferrite Bead, 2500 ohm @ 100 MHz, 0.15 A, 0603; Manufacturer: MuRata; ZTyp@100MHz_Ohm: 2.5k; SizeAreaWB_mm2: 4.68; DCR_ohm: 1.5; Value1: 1.5 ohm; Imax_A: 150mA; SizeZ_mm: 1; SizeX_mm: 1.6; SizeY_mm: 0.8; Value2: 0.15A; SizeArea_mm2: 1.28
R91 = CMP-0020803-2: as R67 on sheet Sht04--FPGA Power Supply
R92 R100 R103 = CMP-0027945-1: RES, 10.0 k, 1%, 0.05 W, 0201; Manufacturer: Yageo America; Power_W: 50mW; TempCo: 200 ppm/C; Value_Code: 10k0; U/M: EA; Value: 10.0k; EIA_Code: E96; Res_ohm: 10k; SizeX_mm: 0.6; SizeY_mm: 0.3; SizeZ_mm: 0.26; Value2: 0.05W; SizeArea_mm2: 0.18; AEC Qualified: N; VDC_V: 25V; AEC Category: Q200
R93 R104 R105 R113 R150 R152 = CMP-0025885-5: RES, 0, 5%, 0.1 W, 0603; Manufacturer: Yageo; Power_W: 100mW; TempCo: 200 ppm/C; Value_Code: 0000; Value: 0; EIA_Code: E24; SizeX_mm: 1.6; SizeZ_mm: 1; Value2: 0.1W; SizeArea_mm2: 1.28; AEC Qualified: N; VDC_V: 75V; AEC Category: Q200; SizeY_mm: 0.8; SizeAreaWB_mm2: 4.68
R94 R106 R108 R110 R111 R192 = CMP-0027008-1: as R189-R191 on sheet Sht04--FPGA Power Supply
R95 = CMP-0028099-1: RES, 301 k, 1%, 0.05 W, 0201; Manufacturer: Yageo America; Power_W: 50mW; TempCo: 200 ppm/C; U/M: EA; Value: 301k; EIA_Code: E96; SizeX_mm: 0.6; SizeY_mm: 0.3; SizeZ_mm: 0.26; Value2: 0.05W; SizeArea_mm2: 0.18; AEC Qualified: N; VDC_V: 25V; AEC Category: Q200
R96 = CMP-0027720-1: RES, 475 k, 1%, 0.05 W, 0201; Manufacturer: Yageo America; Power_W: 50mW; TempCo: 200 ppm/C; U/M: EA; Value: 475k; EIA_Code: E96; SizeX_mm: 0.6; SizeY_mm: 0.3; SizeZ_mm: 0.26; Value2: 0.05W; SizeArea_mm2: 0.18; AEC Qualified: N; VDC_V: 25V; AEC Category: Q200
R97 = CMP-0027636-1: RES, 374 k, 1%, 0.05 W, 0201; Manufacturer: Yageo America; Power_W: 50mW; TempCo: 200 ppm/C; U/M: EA; Value: 374k; EIA_Code: E96; SizeX_mm: 0.6; SizeY_mm: 0.3; SizeZ_mm: 0.26; Value2: 0.05W; SizeArea_mm2: 0.18; AEC Qualified: N; VDC_V: 25V; AEC Category: Q200
R98 = CMP-0027901-1: RES, 86.6 k, 1%, 0.05 W, 0201; Manufacturer: Yageo America; Power_W: 50mW; TempCo: 200 ppm/C; Value_Code: 86k6; U/M: EA; Value: 86.6k; EIA_Code: E96; SizeX_mm: 0.6; SizeY_mm: 0.3; SizeZ_mm: 0.26; Value2: 0.05W; SizeArea_mm2: 0.18; AEC Qualified: N; VDC_V: 25V; AEC Category: Q200
R99 = CMP-0027450-1: RES, 1.80 k, 1%, 0.05 W, 0201; Manufacturer: Yageo America; Power_W: 50mW; TempCo: 200 ppm/C; Value_Code: 1k80; U/M: EA; Value: 1.80k; Res_ohm: 1.8k; SizeX_mm: 0.6; SizeY_mm: 0.3; SizeZ_mm: 0.26; Value2: 0.05W; SizeArea_mm2: 0.18; AEC Qualified: N; VDC_V: 25V; AEC Category: Q200
R101 = CMP-0027606-1: RES, 32.4 k, 1%, 0.05 W, 0201; Manufacturer: Yageo America; Power_W: 50mW; TempCo: 200 ppm/C; Value_Code: 32k4; U/M: EA; Value: 32.4k; EIA_Code: E96; SizeX_mm: 0.6; SizeY_mm: 0.3; SizeZ_mm: 0.26; Value2: 0.05W; SizeArea_mm2: 0.18; AEC Qualified: N; VDC_V: 25V; AEC Category: Q200
R102 = CMP-0027696-1: RES, 42.2 k, 1%, 0.05 W, 0201; Manufacturer: Yageo America; Power_W: 50mW; TempCo: 200 ppm/C; Value_Code: 42k2; U/M: EA; Value: 42.2k; EIA_Code: E96; SizeX_mm: 0.6; SizeY_mm: 0.3; SizeZ_mm: 0.26; Value2: 0.05W; SizeArea_mm2: 0.18; AEC Qualified: N; VDC_V: 25V; AEC Category: Q200
R107 = CMP-0026828-1: RES, 110 k, 5%, 0.063 W, 0402; Manufacturer: Vishay-Dale; Power_W: 63mW; TempCo: 200 ppm/C; U/M: EA; Value: 110k; EIA_Code: E24; SizeX_mm: 1; SizeY_mm: 0.5; SizeZ_mm: 0.6; Value2: 0.063W; VDC_V: 50V; AEC Category: Q200
R109 = CMP-0027529-1: RES, 26.1 k, 1%, 0.05 W, 0201; Manufacturer: Yageo America; Power_W: 50mW; TempCo: 200 ppm/C; Value_Code: 26k1; U/M: EA; Value: 26.1k; EIA_Code: E96; SizeX_mm: 0.6; SizeY_mm: 0.3; SizeZ_mm: 0.26; Value2: 0.05W; SizeArea_mm2: 0.18; AEC Qualified: N; VDC_V: 25V; AEC Category: Q200
R112 = CMP-0026725-1: RES, 1.00 k, 1%, 0.0625 W, 0402; Manufacturer: Yageo America; Power_W: 62.5mW; TempCo: 100 ppm/C; Value_Code: 1k00; U/M: EA; Value: 1.00k; EIA_Code: E96; Res_ohm: 1k; SizeX_mm: 1; SizeY_mm: 0.5; SizeZ_mm: 0.6; AEC Qualified: N; VDC_V: 50V; AEC Category: Q200
R151 = CMP-0026071-3: as R164 on sheet Sht05--TX-RX Supply 1.8V and 1.15V
U15 = CMP-0013943-2: 20 Vout Fully Integration Synchronous Boost Converter with 8 A Switch Current, RNW0013A (VQFN-HR-13); Manufacturer: Texas Instruments; Alternate PartNumber: TPS61178RNWT; SizeX_mm: 3.5; SizeY_mm: 3; CompType: IC; SizeZ_mm: 1; SizeArea_mm2: 10.5; SizeAreaWB_mm2: 18; U/M: EA
U16 = CMP-0013435-7: Dual, 150mA, Wide-Vin, Positive and Negative Low-Dropout (LDO) Voltage Regulator, DSC0010J (WSON-10); Alternate Manufacturer: Texas Instruments; Alternate PartNumber: TPS7A3901DSCT; Rating: Catalog; CompType: IC; SizeAreaWB_mm2: 16.0; SizeY_mm: 3.0; AEC Qualified: N; SizeZ_mm: 0.8; SizeArea_mm2: 9.0; AEC Category: Q200
U17 = CMP-0065261-6: 36-V 1-A Step-Down DC-DC Nano Module, SIL0010A (uSIP-10); Manufacturer: Texas Instruments; Alternate PartNumber: LMZM23601SILT; SizeX_mm: 3.8; SizeY_mm: 3.0; CompType: IC; SizeZ_mm: 1.578; SizeArea_mm2: 11.4; SizeAreaWB_mm2: 19.2; AEC Category: Q200; AEC Qualified: N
